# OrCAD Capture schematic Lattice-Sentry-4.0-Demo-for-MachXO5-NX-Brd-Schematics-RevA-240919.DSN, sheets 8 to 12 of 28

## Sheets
8 LFMXO5D Bank3,4: size B
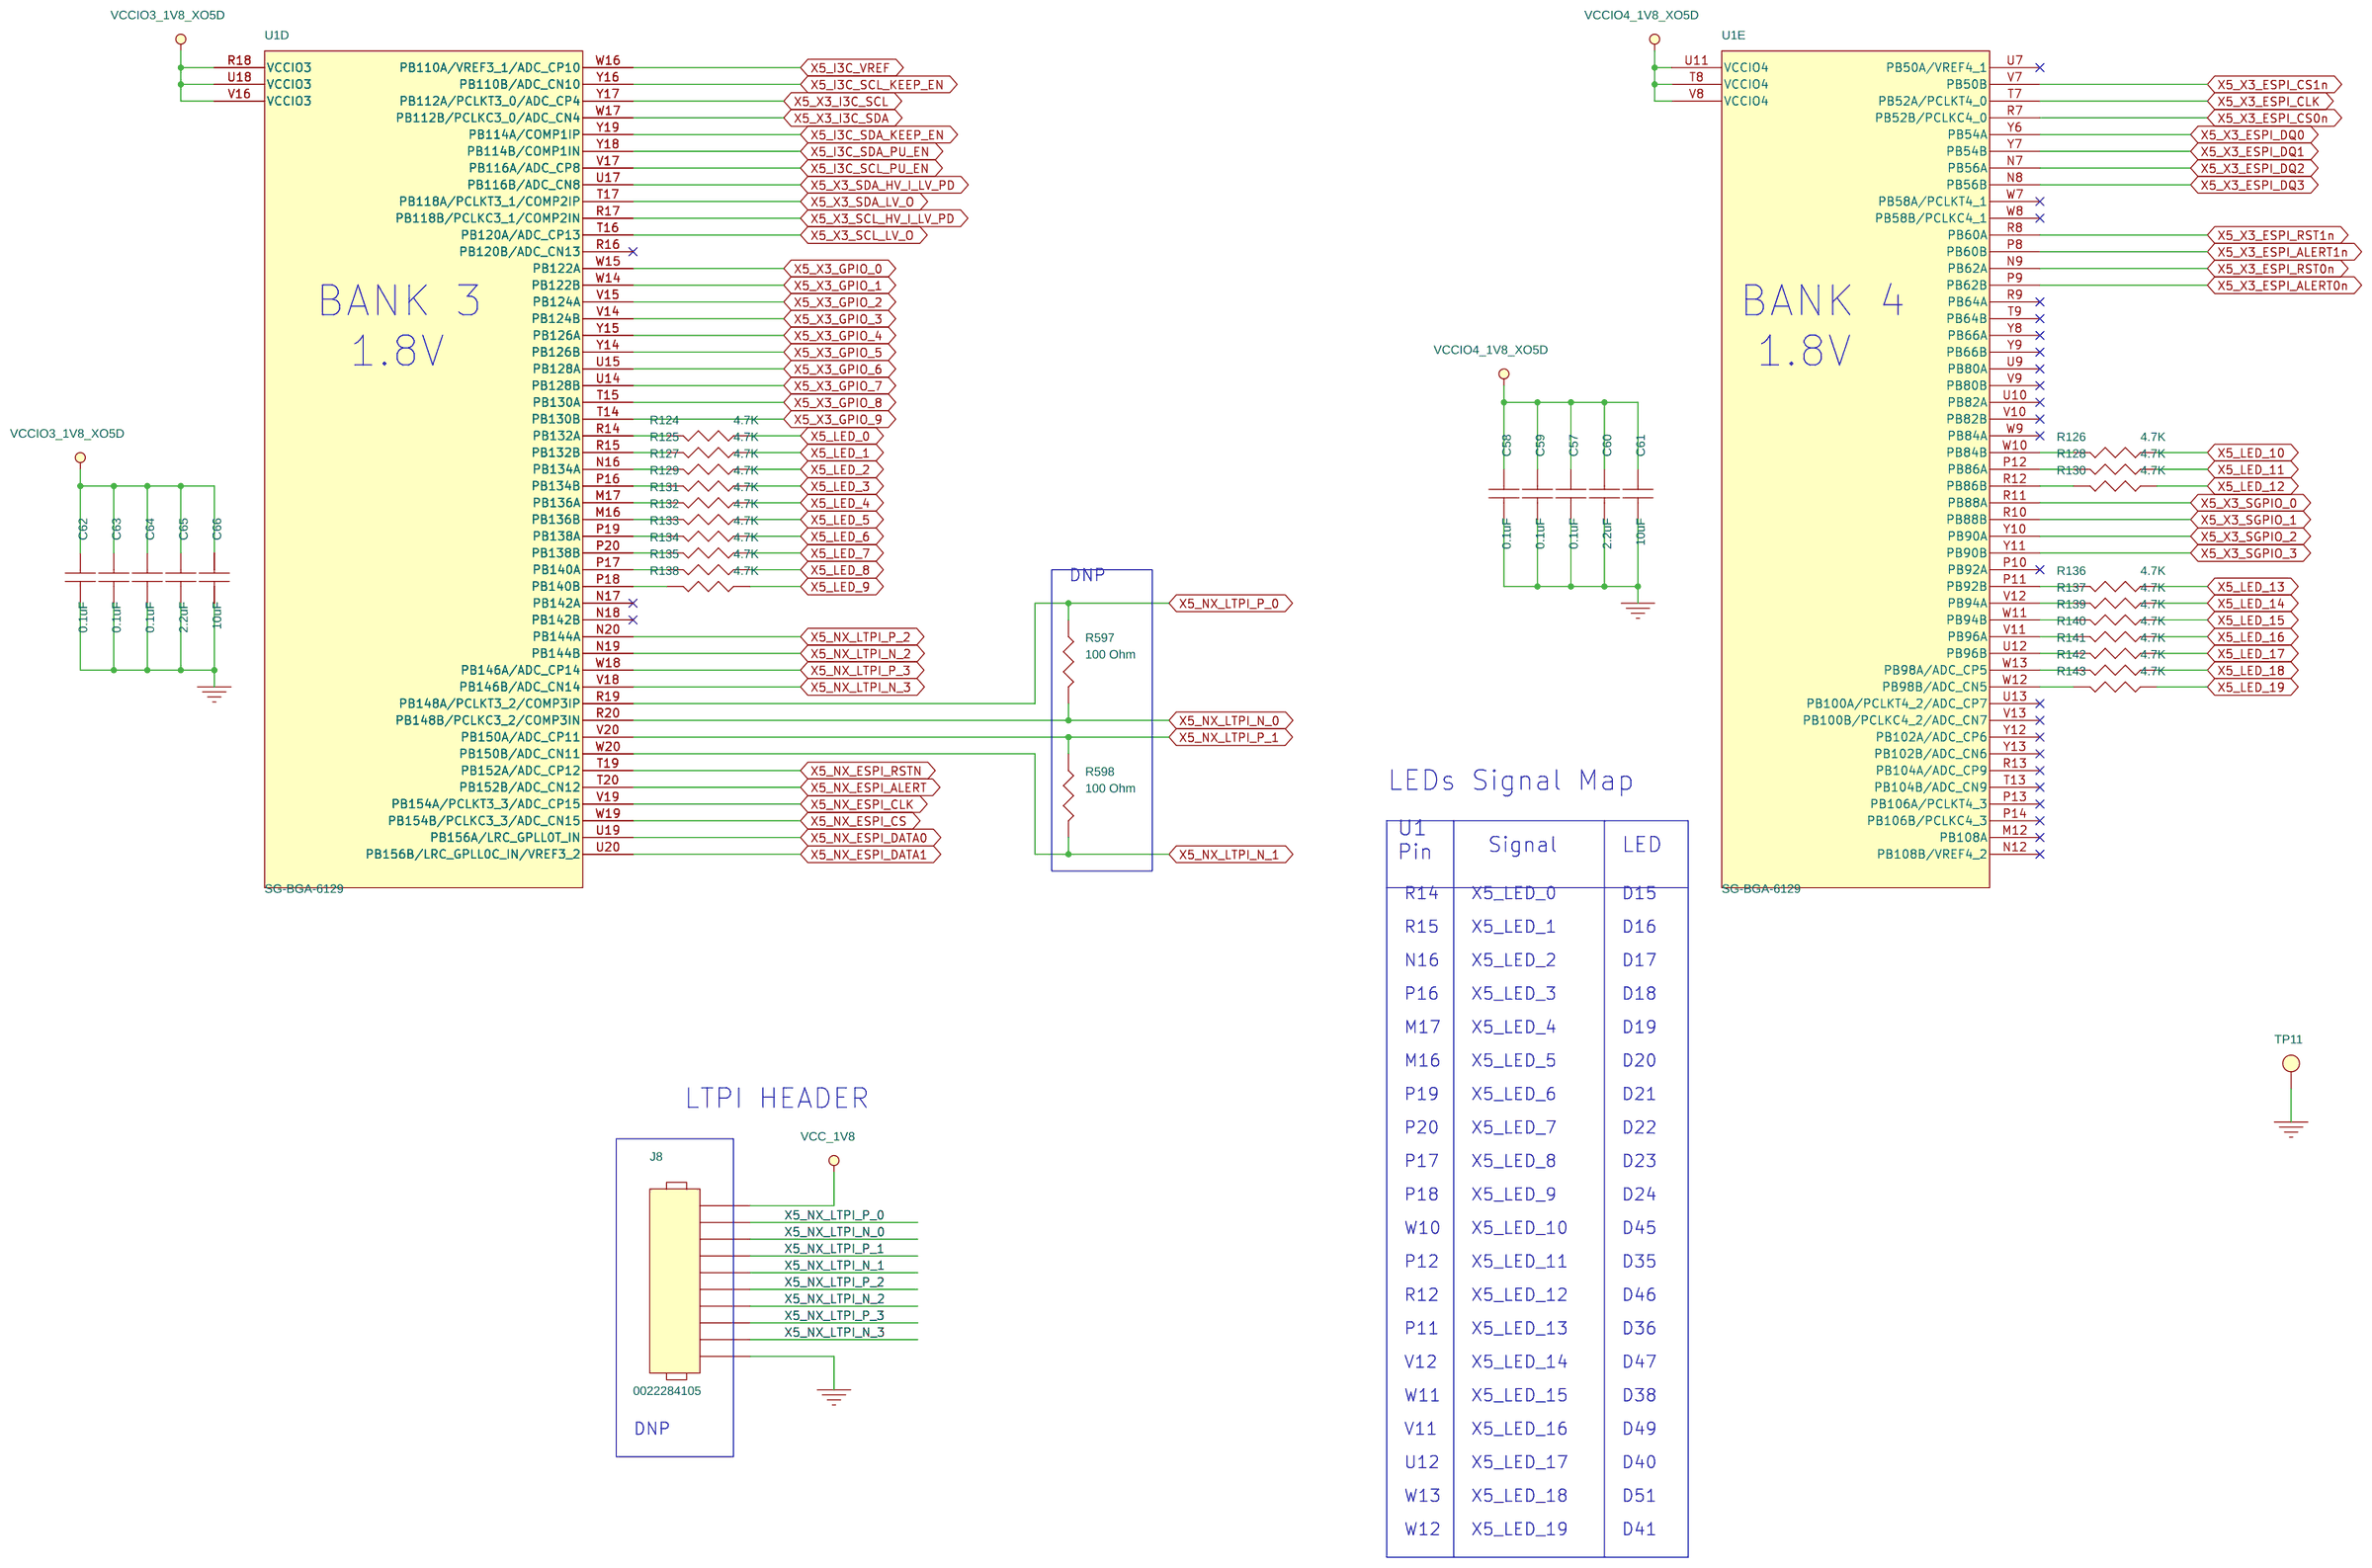
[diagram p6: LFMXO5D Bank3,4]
9 LFMXO5D Power: size B
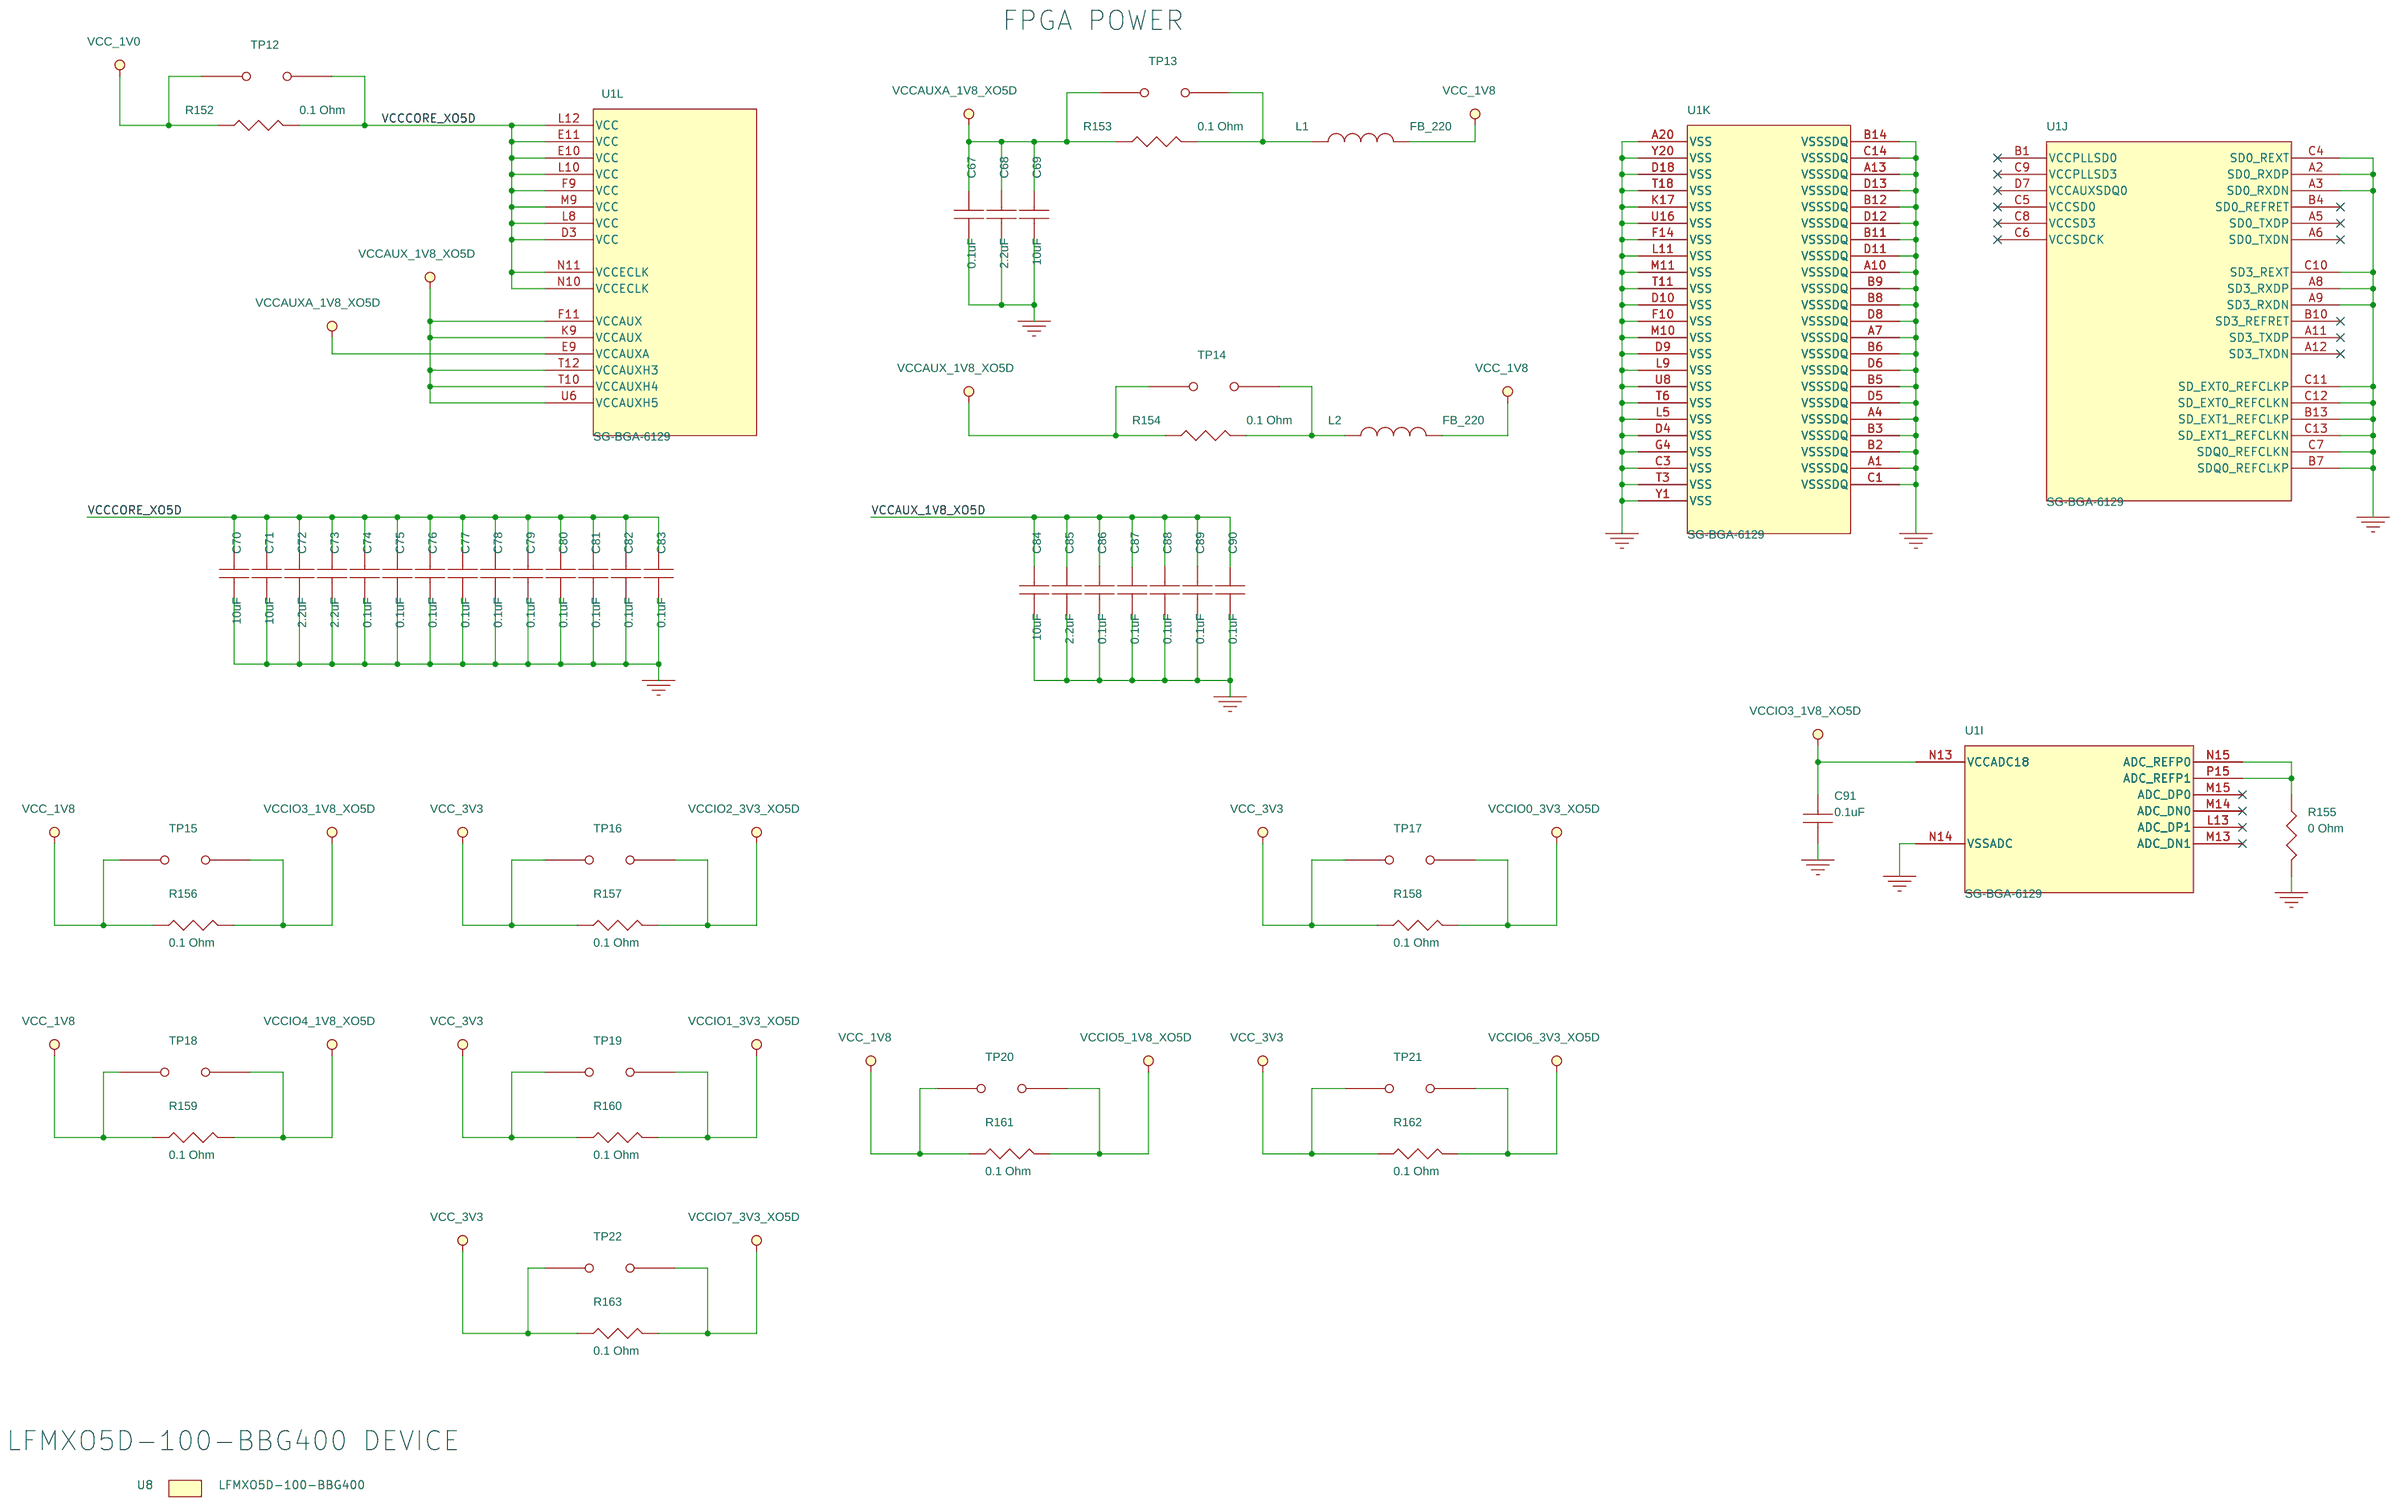
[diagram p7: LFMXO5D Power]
10 Demo FTDI: size B
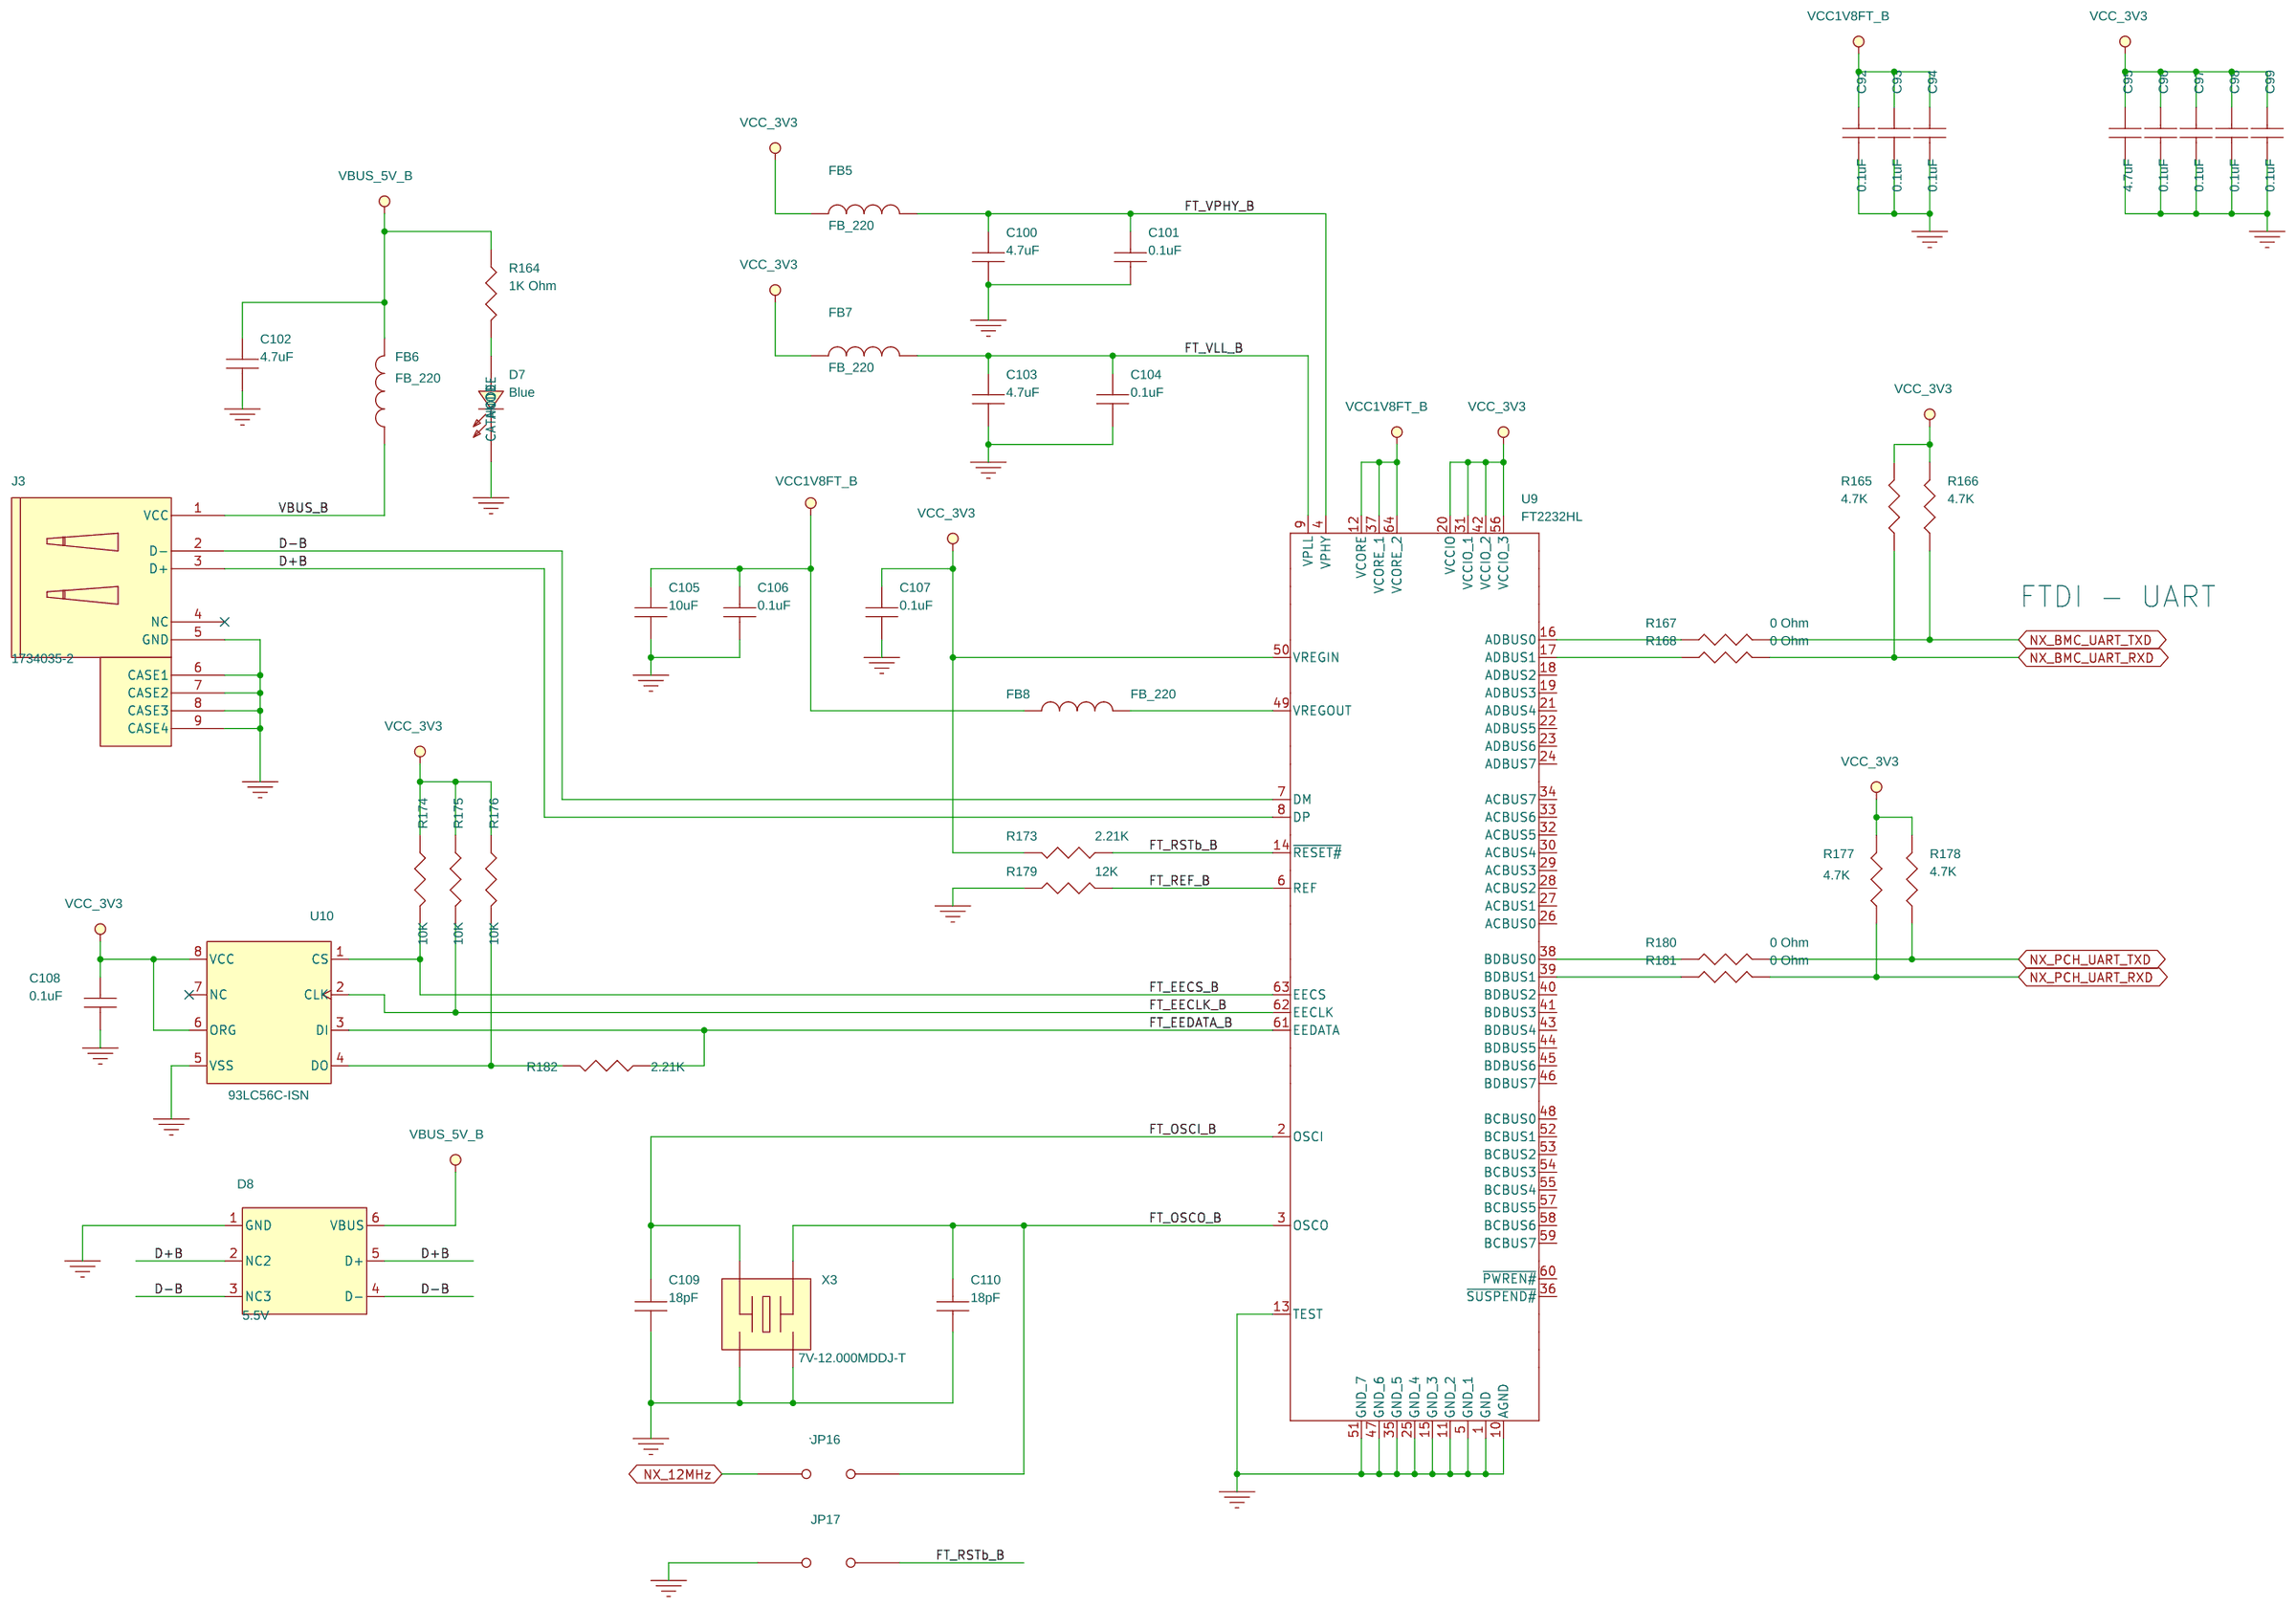
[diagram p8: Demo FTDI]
11 CertusPro-NX Bank1,5 (BMC): size B
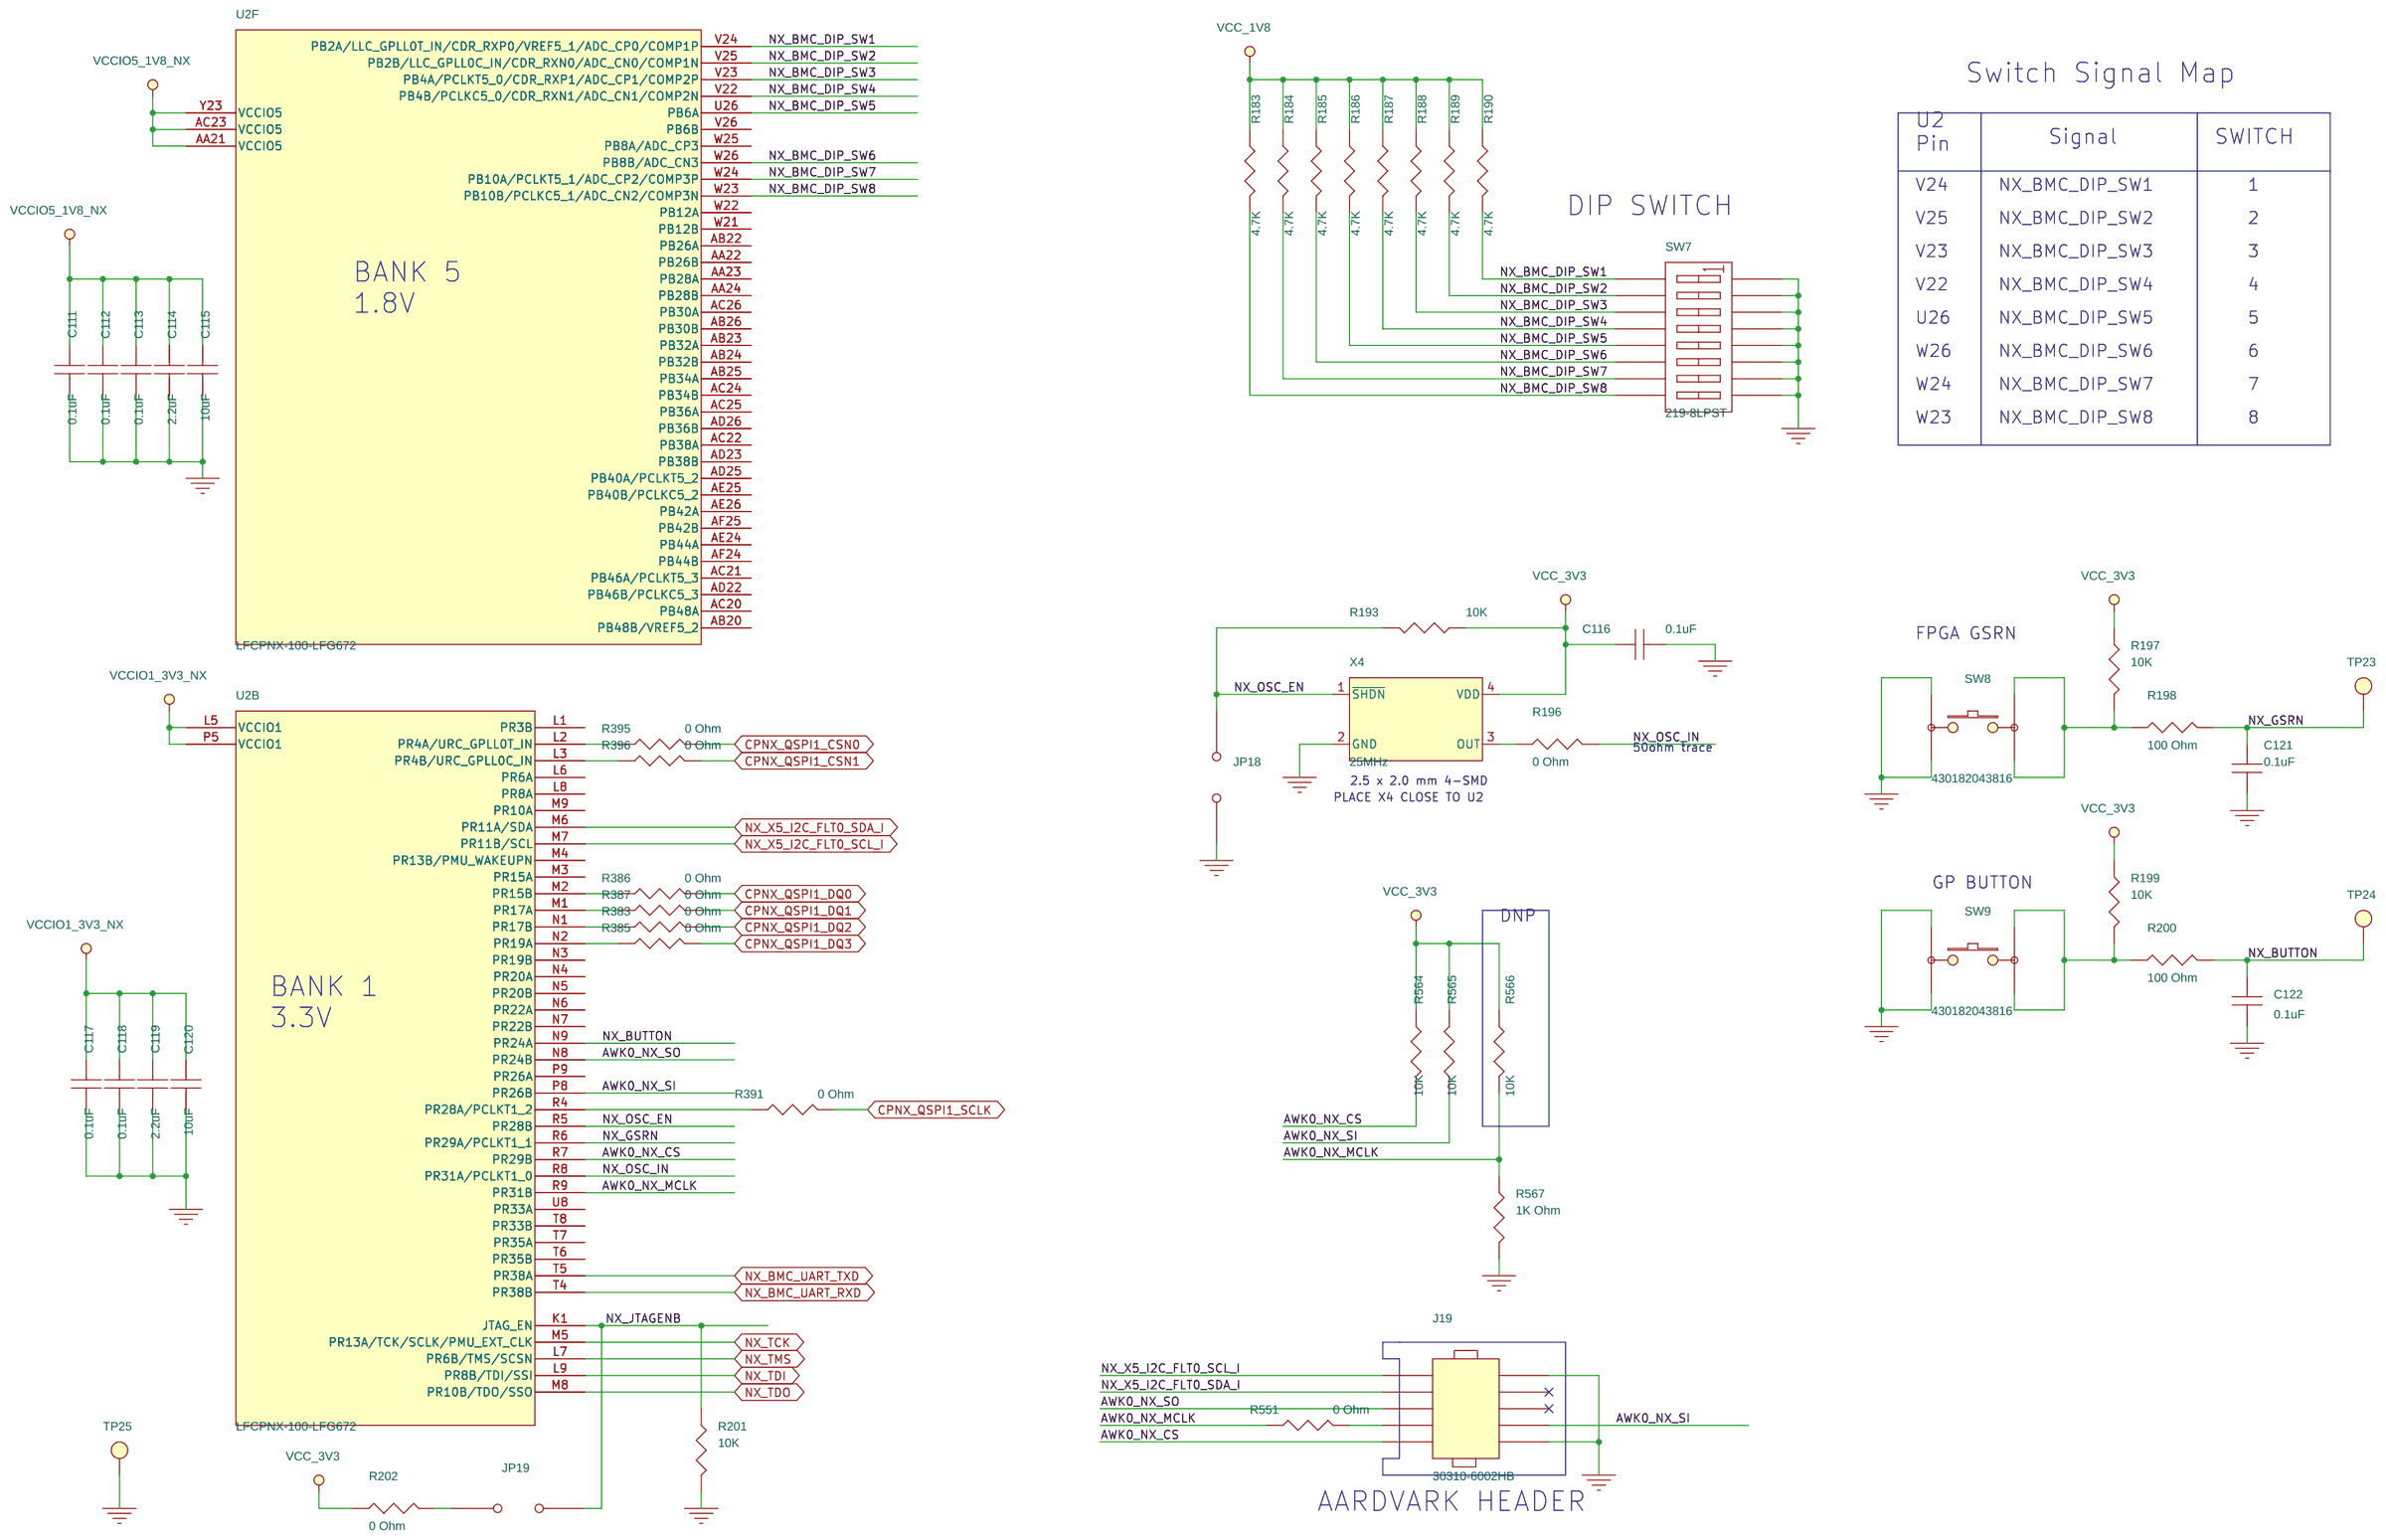
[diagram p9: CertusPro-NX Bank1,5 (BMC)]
12 CertusPro-NX Bank0 (BMC): size B
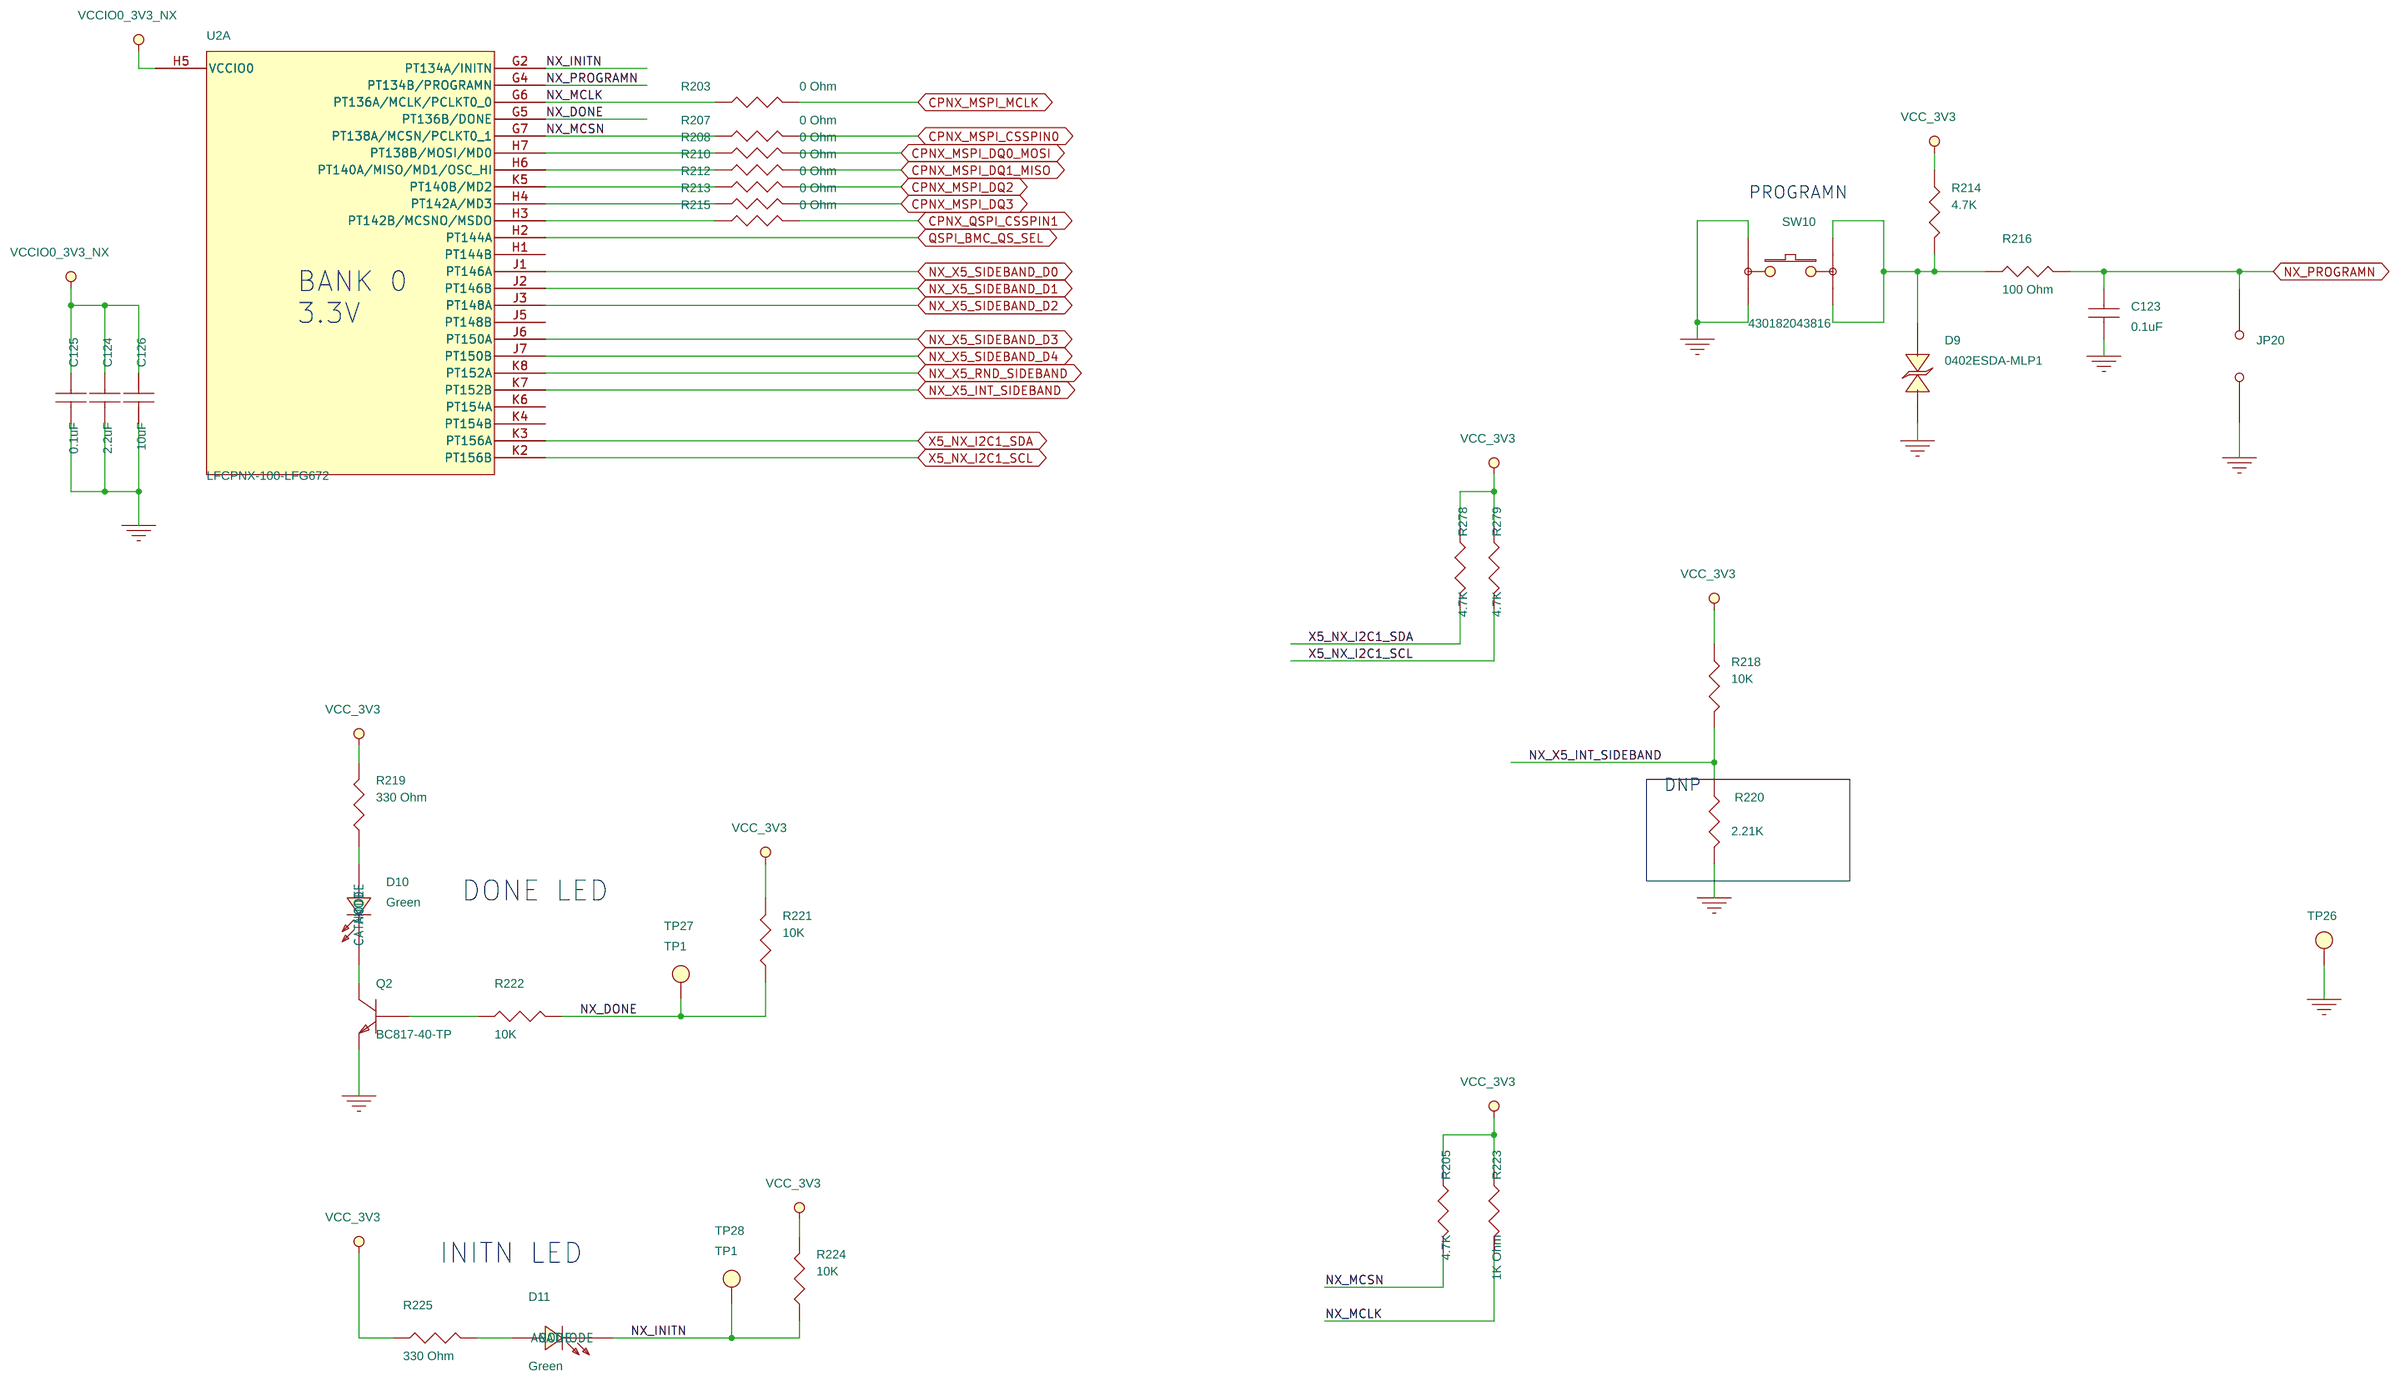
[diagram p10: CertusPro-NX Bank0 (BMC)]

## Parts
sheet Certus Pro NX Power
U2  LFCPNX-100-LFG672  [fcBGA-100p27x27-672]  (sections A,B,C,D,E,F,G,H,I,J,K,L,M,N,O)
sheet CertusPro-NX Bank0 (BMC)
C123  0.1uF  [C0402-L]
C124  2.2uF  [C0603-L]
C125  0.1uF  [C0402-L]
C126  10uF  [C0805-L]
D9  0402ESDA-MLP1  [TVS0402]
D10  Green  [LED0603]
D11  Green  [LED0603]
JP20  Jumper  [CONN2_M20-999_1x2_HRW]
Q2  BC817-40-TP  [SOT-23-3]
R203  0 Ohm  [R0402-L]
R205  4.7K  [R0402-L]
R207  0 Ohm  [R0402-L]
R208  0 Ohm  [R0402-L]
R210  0 Ohm  [R0402-L]
R212  0 Ohm  [R0402-L]
R213  0 Ohm  [R0402-L]
R214  4.7K  [R0402-L]
R215  0 Ohm  [R0402-L]
R216  100 Ohm  [R0402-L]
R218  10K  [R0402-L]
R219  330 Ohm  [R0402-L]
R220  2.21K  [R0402-L]
R221  10K  [R0402-L]
R222  10K  [R0402-L]
R223  1K Ohm  [R0402-L]
R224  10K  [R0402-L]
R225  330 Ohm  [R0402-L]
R278  4.7K  [R0402-L]
R279  4.7K  [R0402-L]
SW10  430182043816  [SOIC_82043816_WRE]
TP26  TP1  [TPd39c60]
TP27  TP1  [TPd39c60]
TP28  TP1  [TPd39c60]
sheet CertusPro-NX Bank1,5 (BMC)
C111  0.1uF  [C0402-L]
C112  0.1uF  [C0402-L]
C113  0.1uF  [C0402-L]
C114  2.2uF  [C0603-L]
C115  10uF  [C0805-L]
C116  0.1uF  [C0402-L]
C117  0.1uF  [C0402-L]
C118  0.1uF  [C0402-L]
C119  2.2uF  [C0603-L]
C120  10uF  [C0805-L]
C121  0.1uF  [C0402-L]
C122  0.1uF  [C0402-L]
J19  30310-6002HB  [CONN_30310-6002HB_3MM]
JP18  Jumper  [CONN2_M20-999_1x2_HRW]
JP19  Jumper  [CONN2_M20-999_1x2_HRW]
R183  4.7K  [R0402-L]
R184  4.7K  [R0402-L]
R185  4.7K  [R0402-L]
R186  4.7K  [R0402-L]
R187  4.7K  [R0402-L]
R188  4.7K  [R0402-L]
R189  4.7K  [R0402-L]
R190  4.7K  [R0402-L]
R193  10K  [R0402-L]
R196  0 Ohm  [R0402-L]
R197  10K  [R0402-L]
R198  100 Ohm  [R0402-L]
R199  10K  [R0402-L]
R200  100 Ohm  [R0402-L]
R201  10K  [R0402-L]
R202  0 Ohm  [R0402-L]
R383  0 Ohm  [R0402-L]
R385  0 Ohm  [R0402-L]
R386  0 Ohm  [R0402-L]
R387  0 Ohm  [R0402-L]
R391  0 Ohm  [R0402-L]
R395  0 Ohm  [R0402-L]
R396  0 Ohm  [R0402-L]
R551  0 Ohm  [R0402-L]
R564  10K  [R0402-L]
R565  10K  [R0402-L]
R566  10K  [R0402-L]
R567  1K Ohm  [R0402-L]
SW7  219-8LPST  [219-8LPST_CTS]
SW8  430182043816  [SOIC_82043816_WRE]
SW9  430182043816  [SOIC_82043816_WRE]
TP23  TP1  [TPd39c60]
TP24  TP1  [TPd39c60]
TP25  TP1  [TPd39c60]
X4  25MHz  [ECS-2520MV_ECS]
sheet Demo FTDI
C92  0.1uF  [C0402-L]
C93  0.1uF  [C0402-L]
C94  0.1uF  [C0402-L]
C95  4.7uF  [C0603-L]
C96  0.1uF  [C0402-L]
C97  0.1uF  [C0402-L]
C98  0.1uF  [C0402-L]
C99  0.1uF  [C0402-L]
C100  4.7uF  [C0603-L]
C101  0.1uF  [C0402-L]
C102  4.7uF  [C0603-L]
C103  4.7uF  [C0603-L]
C104  0.1uF  [C0402-L]
C105  10uF  [C0805-L]
C106  0.1uF  [C0402-L]
C107  0.1uF  [C0402-L]
C108  0.1uF  [C0402-L]
C109  18pF  [C0402-L]
C110  18pF  [C0402-L]
D7  Blue  [LED0603]
D8  5.5V  [UDFN6_1P2X1]
FB5  FB_220  [IND_1608_TDK]
FB6  FB_220  [IND_1608_TDK]
FB7  FB_220  [IND_1608_TDK]
FB8  FB_220  [IND_1608_TDK]
J3  1734035-2  [CONN5_USB1734035_TEC]
JP16  Jumper  [CONN2_M20-999_1x2_HRW]
JP17  Jumper  [CONN2_M20-999_1x2_HRW]
R164  1K Ohm  [R0402-L]
R165  4.7K  [R0402-L]
R166  4.7K  [R0402-L]
R167  0 Ohm  [R0402-L]
R168  0 Ohm  [R0402-L]
R173  2.21K  [R0402-L]
R174  10K  [R0402-L]
R175  10K  [R0402-L]
R176  10K  [R0402-L]
R177  4.7K  [R0402-L]
R178  4.7K  [R0402-L]
R179  12K  [R0402-L]
R180  0 Ohm  [R0402-L]
R181  0 Ohm  [R0402-L]
R182  2.21K  [R0402-L]
U9  FT2232HL  [64L-LQFP]
U10  93LC56C-ISN  [SOIC8-N]
X3  7V-12.000MDDJ-T  [SMD_0MAHE-T_TXC-L]
sheet LFMXO5D Bank3,4
C57  0.1uF  [C0402-L]
C58  0.1uF  [C0402-L]
C59  0.1uF  [C0402-L]
C60  2.2uF  [C0603-L]
C61  10uF  [C0805-L]
C62  0.1uF  [C0402-L]
C63  0.1uF  [C0402-L]
C64  0.1uF  [C0402-L]
C65  2.2uF  [C0603-L]
C66  10uF  [C0805-L]
J8  0022284105  [22-28-4105_MOL]
R124  4.7K  [R0402-L]
R125  4.7K  [R0402-L]
R126  4.7K  [R0402-L]
R127  4.7K  [R0402-L]
R128  4.7K  [R0402-L]
R129  4.7K  [R0402-L]
R130  4.7K  [R0402-L]
R131  4.7K  [R0402-L]
R132  4.7K  [R0402-L]
R133  4.7K  [R0402-L]
R134  4.7K  [R0402-L]
R135  4.7K  [R0402-L]
R136  4.7K  [R0402-L]
R137  4.7K  [R0402-L]
R138  4.7K  [R0402-L]
R139  4.7K  [R0402-L]
R140  4.7K  [R0402-L]
R141  4.7K  [R0402-L]
R142  4.7K  [R0402-L]
R143  4.7K  [R0402-L]
R597  100 Ohm  [R0402-L]
R598  100 Ohm  [R0402-L]
TP11  TP1  [TPd39c60]
sheet LFMXO5D Bank5,7
U1  SG-BGA-6129  [bga400_socket]  (sections A,B,C,D,E,F,G,H,I,J,K,L)
sheet LFMXO5D Power
C67  0.1uF  [C0402-L]
C68  2.2uF  [C0603-L]
C69  10uF  [C0805-L]
C70  10uF  [C0805-L]
C71  10uF  [C0805-L]
C72  2.2uF  [C0603-L]
C73  2.2uF  [C0603-L]
C74  0.1uF  [C0402-L]
C75  0.1uF  [C0402-L]
C76  0.1uF  [C0402-L]
C77  0.1uF  [C0402-L]
C78  0.1uF  [C0402-L]
C79  0.1uF  [C0402-L]
C80  0.1uF  [C0402-L]
C81  0.1uF  [C0402-L]
C82  0.1uF  [C0402-L]
C83  0.1uF  [C0402-L]
C84  10uF  [C0805-L]
C85  2.2uF  [C0603-L]
C86  0.1uF  [C0402-L]
C87  0.1uF  [C0402-L]
C88  0.1uF  [C0402-L]
C89  0.1uF  [C0402-L]
C90  0.1uF  [C0402-L]
C91  0.1uF  [C0402-L]
L1  FB_220  [IND_1608_TDK]
L2  FB_220  [IND_1608_TDK]
R152  0.1 Ohm  [R0603-L]
R153  0.1 Ohm  [R0603-L]
R154  0.1 Ohm  [R0603-L]
R155  0 Ohm  [R0402-L]
R156  0.1 Ohm  [R0603-L]
R157  0.1 Ohm  [R0603-L]
R158  0.1 Ohm  [R0603-L]
R159  0.1 Ohm  [R0603-L]
R160  0.1 Ohm  [R0603-L]
R161  0.1 Ohm  [R0603-L]
R162  0.1 Ohm  [R0603-L]
R163  0.1 Ohm  [R0603-L]
TP12  Jumper  [CONN2_M20-999_1x2_HRW]
TP13  Jumper  [CONN2_M20-999_1x2_HRW]
TP14  Jumper  [CONN2_M20-999_1x2_HRW]
TP15  Jumper  [CONN2_M20-999_1x2_HRW]
TP16  Jumper  [CONN2_M20-999_1x2_HRW]
TP17  Jumper  [CONN2_M20-999_1x2_HRW]
TP18  Jumper  [CONN2_M20-999_1x2_HRW]
TP19  Jumper  [CONN2_M20-999_1x2_HRW]
TP20  Jumper  [CONN2_M20-999_1x2_HRW]
TP21  Jumper  [CONN2_M20-999_1x2_HRW]
TP22  Jumper  [CONN2_M20-999_1x2_HRW]
U8  LFMXO5D-100-BBG400

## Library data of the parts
U2 = LFCPNX-100-LFG672: Lattice Lattice CertusPro-NX General Purpose FPGA on Nexus platform (28nm FD-SOI); MFR PART NO.: LFCPNX-100-9LFG672I; Manufacturer: Lattice Semiconductor; Manufacturer Part Number: LFCPNX-100-9LFG672C; PACKAGE: LFG672; PART DESCRIPTION: IC FPGA CERTUSPRO-NX; Part Number: LFCPNX-100-9LFG672C; Part Type: FPGA; Datasheet: https://www.latticesemi.com/view_document?document_id=53126
C57-C59 C62-C64 C67 C74-C83 C86-C94 C96-C99 C101 C104 C106-C108 C111-C113 C116-C118 C121-C123 C125 = CAP_NP: 0.1 µF ±10% 50V Ceramic Capacitor X7R 0402 (1005 Metric); Manufacturer: Murata; Manufacturer Part Number: GRM155R71H104KE14J; Part Number: GRM155R71H104KE14J; Part type: Ceramic; Tolerance: 10%; Voltage: 50V; Datasheet: https://search.murata.co.jp/Ceramy/image/img/A01X/G101/ENG/GRM155R71H104KE14-01.pdf
C60 C65 C68 C72 C73 C85 C114 C119 C124 = CAP_NP: 2.2 µF ±10% 25V Ceramic Capacitor X5R 0603 (1608 Metric); Manufacturer: Murata; Manufacturer Part Number: GRM188R61E225KA12J; Part Number: GRM188R61E225KA12J; Part type: Ceramic; Tolerance: 10%; Voltage: 25V; Datasheet: https://search.murata.co.jp/Ceramy/image/img/A01X/G101/ENG/GRM188R61E225KA12-01.pdf
C61 C66 C69-C71 C84 C105 C115 C120 C126 = CAP_NP: 10 µF ±10% 25V Ceramic Capacitor X5R 0805 (2012 Metric); Manufacturer: Murata; Manufacturer Part Number: GRM21BR61E106KA73K; Part Number: GRM21BR61E106KA73K; Part type: Ceramic; Tolerance: 10%; Voltage: 25V; Datasheet: https://search.murata.co.jp/Ceramy/image/img/A01X/G101/ENG/GRM21BR61E106KA73-01.pdf
D9 = DIODE_TS_BI-DIR: SUPPRESSOR ESD 30VDC 0402 HFREE; Manufacturer: Eaton; Part type: ESD; Voltage: 30V; Datasheet: https://www.eaton.com/content/dam/eaton/products/electronic-components/resources/data-sheet/eaton-0402esda-mlp-esd-suppressor-data-sheet.pdf
D10 D11 = LED_0: Green 572nm LED indication - Discrete  2.2V 0603; Manufacturer: Rohm Semiconductor; Manufacturer Part Number: SML-D12M8WT86; Part Number: SML-D12M8WT86; Part type: LED; Voltage: 2.2V; Datasheet: https://fscdn.rohm.com/en/products/databook/datasheet/opto/led/chip_mono/sml-d12x8_d13x8-e.pdf
JP20 = JUMPER: Connector Header Through Hole 2 position 0.100" (2.54mm); Manufacturer: Sullins; Manufacturer Part Number: PREC002SAAN-RC; Part Number: PREC002SAAN-RC; Datasheet: https://media.digikey.com/PDF/Data%20Sheets/Sullins%20PDFs/z%20RzCzzzSzzN-RC,%20ST,11635-B.pdf
Q2 = NPN_BEC_0: Bipolar (BJT) Transistor NPN 45 V 800 mA 100MHz 310 mW Surface Mount SOT-23; Manufacturer: Micro Commercial; Part Type: BJT_NPN; Datasheet: https://www.mccsemi.com/pdf/Products/BC817-16~BC817-40(SOT-23).pdf
R155 R167 R168 R180 R181 R196 R202 R203 R207 R208 R210 R212 R213 R215 R383 R385-R387 R391 R395 R396 R551 = R: 0 Ohms Jumper Chip Resistor 0402 (1005 Metric) Moisture Resistant Thick Film; Manufacturer: Yageo; Manufacturer Part Number: RC0402FR-070RL; Part Number: RC0402FR-070RL; Part type: Thick Film; Datasheet: https://www.yageo.com/upload/media/product/productsearch/datasheet/rchip/PYu-RC_Group_51_RoHS_L_12.pdf
R124-R143 R183-R190 R205 R214 R278 R279 = R: 4.7 kOhms ±1% 0.063W, 1/16W Chip Resistor 0402 (1005 Metric) Thick Film; Manufacturer: Yageo; Manufacturer Part Number: RC0402FR-074K7P; Part Number: RC0402FR-074K7P; Part type: Thick Film; Power: 1/16W; Tolerance: 1%; Datasheet: https://www.yageo.com/upload/media/product/products/datasheet/rchip/PYu-RC_51_RoHS_P_4.pdf
R198 R200 R216 = R: 100 Ohms ±1% 0.063W, 1/16W Chip Resistor 0402 (1005 Metric) Thick Film; Manufacturer: Yageo; Manufacturer Part Number: RC0402FR-07100KP; Part Number: RC0402FR-07100KP; Part type: Thick Film; Power: 1/16W; Tolerance: 1%; Datasheet: https://www.yageo.com/upload/media/product/productsearch/datasheet/rchip/PYu-RC_Group_51_RoHS_L_12.pdf
R174-R176 R197 R199 R201 R218 R221 R222 R224 R564 R565 = R: 10 kOhms ±1% 0.063W, 1/16W Chip Resistor 0402 (1005 Metric) Thick Film; Manufacturer: Yageo; Manufacturer Part Number: RC0402FR-0710KP; Part Number: RC0402FR-0710KP; Part type: Thick Film; Power: 1/16W; Tolerance: 1%; Datasheet: https://www.yageo.com/upload/media/product/products/datasheet/rchip/PYu-RC_51_RoHS_P_4.pdf
R219 R225 = R: 330 Ohms ±1% 0.063W, 1/16W Chip Resistor 0402 (1005 Metric) Moisture Resistant Thick Film; Manufacturer: Yageo; Manufacturer Part Number: RC0402FR-07330RL; Part Number: RC0402FR-07330RL; Part type: Thick Film; Power: 1/16W; Tolerance: 1%; Datasheet: https://www.yageo.com/upload/media/product/productsearch/datasheet/rchip/PYu-RC_Group_51_RoHS_L_12.pdf
R220 = R: 2.21 kOhms ±1% 0.063W, 1/16W Chip Resistor 0402 (1005 Metric) Thick Film; Assy: DNL; Manufacturer: Yageo; Manufacturer Part Number: RC0402FR-072K21L; Part Number: RC0402FR-072K21L; Part type: Thick Film; Power: 1/16W; Tolerance: 1%; Datasheet: https://www.yageo.com/upload/media/product/productsearch/datasheet/rchip/PYu-RC_Group_51_RoHS_L_12.pdf
R223 = R: 1 kOhms ±1% 0.063W, 1/16W Chip Resistor 0402 (1005 Metric) Thick Film; MFR PART NO.: RC0603FR-071KL; Manufacturer: Yageo; Manufacturer Part Number: RC0402FR-71K2P / RC0402FR-0733R2P; PACKAGE: 0603; PART DESCRIPTION: RES 1K OHM 1% 1/10W 0603; Part Number: RC0402FR-071KP / RC0402FR-0733R2P / RC0402FR-0733R2P; Part type: Thick Film; Power: 1/16W; Tolerance: 1%; Datasheet: https://www.yageo.com/upload/media/product/products/datasheet/rchip/PYu-RC_51_RoHS_P_4.pdf
SW8-SW10 = SW_PB-SPST-2: Tactile Switch SPST-NO Top Actuated Surface Mount; Manufacturer: Wurth; Datasheet: https://www.we-online.com/katalog/datasheet/4301x2xxx8x6.pdf
TP11 TP23-TP28 = TP1: Test Point 0.39"; Manufacturer: NA; Part Type: Test Point; Datasheet: NA
J19 = HEADER_5x2: Connector Header Through Hole 10 position 0.100" (2.54mm); Manufacturer: 3M; Part Type: Connector; Datasheet: https://multimedia.3m.com/mws/media/22504O/3mtm-100-in-loprof-hdr-100x-100strt-ra-4-wall-ts0818.pdf
JP16-JP19 TP12-TP22 = JUMPER: Connector Header Through Hole 2 position 0.100" (2.54mm); MANUFACTURER: Sullins; MFR PART NO.: 61300211121; Manufacturer Part Number: PREC002SAAN-RC; PACKAGE: TH; PART DESCRIPTION: CONN HEADER VERT 2POS 2.54MM; Part Number: PREC002SAAN-RC; Datasheet: https://media.digikey.com/PDF/Data%20Sheets/Sullins%20PDFs/z%20RzCzzzSzzN-RC,%20ST,11635-B.pdf
R193 = R: 10 kOhms ±1% 0.063W, 1/16W Chip Resistor 0402 (1005 Metric) Thick Film; MFR PART NO.: RC1608F103CS; Manufacturer: Yageo; Manufacturer Part Number: RC0402FR-0710KP; PACKAGE: 0603; PART DESCRIPTION: RES SMD 10K OHM 1% 1/10W 0603; Part Number: RC0402FR-0710KP; Part type: Thick Film; Power: 1/16W; Tolerance: 1%; Datasheet: https://www.yageo.com/upload/media/product/products/datasheet/rchip/PYu-RC_51_RoHS_P_4.pdf
R566 = R: 10 kOhms ±1% 0.063W, 1/16W Chip Resistor 0402 (1005 Metric) Thick Film; Assy: DNL; Manufacturer: Yageo; Manufacturer Part Number: RC0402FR-0710KP; Part Number: RC0402FR-0710KP; Part type: Thick Film; Power: 1/16W; Tolerance: 1%; Datasheet: https://www.yageo.com/upload/media/product/products/datasheet/rchip/PYu-RC_51_RoHS_P_4.pdf
R164 R567 = R: 1 kOhms ±1% 0.063W, 1/16W Chip Resistor 0402 (1005 Metric) Thick Film; Manufacturer: Yageo; Manufacturer Part Number: RC0402FR-71K2P / RC0402FR-0733R2P; Part Number: RC0402FR-071KP / RC0402FR-0733R2P / RC0402FR-0733R2P; Part type: Thick Film; Power: 1/16W; Tolerance: 1%; Datasheet: https://www.yageo.com/upload/media/product/products/datasheet/rchip/PYu-RC_51_RoHS_P_4.pdf
SW7 = SW_DIP-8: Dip Switch SPST 8 Position Surface Mount Slide (Standard) Actuator 100mA 20VDC / Dip Switch SPST 5 Position Surface Mount Slide (Standard) Actuator 100mA 20VDC; MFR PART NO.: TDA08H0SB1; Manufacturer: CST; PACKAGE: SMD; PART DESCRIPTION: SWITCH SLIDE DIP SPST 25MA 24V; Datasheet: https://www.ctscorp.com/wp-content/uploads/219.pdf
X4 = OSC4PIN_SM: 25 MHz XO (Standard) HCMOS Oscillator 1.6V ~ 3.6V Enable/Disable 4-SMD, No Lead; Manufacturer: ECS; Manufacturer Part Number: ECS-2520MV-250-CM-TR; Part Number: ECS-2520MV-250-CM-TR; Part Type: Oscillator; Datasheet: https://ecsxtal.com/store/pdf/ECS-3225MV.pdf
C95 C100 C102 C103 = CAP_NP: 4.7 µF ±10% 25V Ceramic Capacitor X5R 0603 (1608 Metric); Manufacturer: TDK; Manufacturer Part Number: C1608X5R1E475K080AC; Part Number: C1608X5R1E475K080AC; Part type: Ceramic; Tolerance: 10%; Voltage: 25V; Datasheet: https://product.tdk.com/system/files/dam/doc/product/capacitor/ceramic/mlcc/catalog/mlcc_commercial_general_en.pdf
C109 C110 = CAP_NP: 18 pF ±5% 50V Ceramic Capacitor C0G, NP0 0402 (1005 Metric); Manufacturer: Yageo; Manufacturer Part Number: CC0402JRNPO9BN180; Part Number: CC0402JRNPO9BN180; Part type: Ceramic; Tolerance: 5%; Voltage: 50V; Datasheet: https://www.yageo.com/upload/media/product/productsearch/datasheet/mlcc/UPY-GP_NP0_16V-to-50V_18.pdf
D7 = LED_0: Blue 470nm LED Indication - Discrete 2.9V 0603 (1608 Metric); Manufacturer: Lumex; Manufacturer Part Number: SMLD12BN1WT86; Part Number: SMLD12BN1WT86; Part type: LED; Voltage: 2.9V; Datasheet: https://www.rohm.com/datasheet?p=SMLD12BN1W&dist=Digi-key&media=referral&source=digi-key.com&campaign=Digi-key
D8 = ESDR0502: Clamp Ipp Tvs Diode Surface Mount 6-UDFN (1.2x1); Current: 100W; MANUFACTURER: ONSEMI; MFR PART NO.: ESDR0502NMUTBG; Manufacturer Part Number: ESDR0502NMUTAG; PACKAGE: 6-UFDFN; PART DESCRIPTION: TVS DIODE 5.5VWM 6UDFN; Part Number: ESDR0502NMUTAG; Part type: TVS; Datasheet: https://www.onsemi.com/pdf/datasheet/esdr0502n-d.pdf
FB5-FB8 L1 L2 = INDUCTOR: 220 Ohms @ 100 MHz 1 Power Line Ferrite Bead 0603 (1608 Metric) 2.2A 50mOhm; Current: 2.2A; DCR: 50 mOhm; Manufacturer: Murata Electronics; Manufacturer Part Number: BLM18KG221SN1D; Part Number: BLM18KG221SN1D; Datasheet: https://www.murata.com/products/productdata/8796738650142/ENFA0003.pdf
J3 = USB_MINI_B: USB - mini B USB 2.0 Receptacle Connector 5 Position Surface Mount, Right Angle; MANUFACTURER: TE Connectivity; MFR PART NO.: 690-005-299-043; PACKAGE: SMD; PART DESCRIPTION: CONN RCPT USB2.0 MINI B SMD R/A; Part Type: Connector; Populate: <Populate>; Datasheet: https://www.te.com/commerce/DocumentDelivery/DDEController?Action=srchrtrv&DocNm=1734035&DocType=Customer+Drawing&DocLang=English
R165 R166 R177 R178 = R: 4.7 kOhms ±1% 0.063W, 1/16W Chip Resistor 0402 (1005 Metric) Thick Film; MFR PART NO.: CRCW06032K20FKEA; Manufacturer: Yageo; Manufacturer Part Number: RC0402FR-074K7P; PACKAGE: 0603; PART DESCRIPTION: RES SMD 2.2K OHM 1% 1/10W 0603; Part Number: RC0402FR-074K7P; Part type: Thick Film; Populate: <Populate>; Power: 1/16W; Tolerance: 1%; Datasheet: https://www.yageo.com/upload/media/product/products/datasheet/rchip/PYu-RC_51_RoHS_P_4.pdf
R173 R182 = R: 2.21 kOhms ±1% 0.063W, 1/16W Chip Resistor 0402 (1005 Metric) Thick Film; Manufacturer: Yageo; Manufacturer Part Number: RC0402FR-072K21L; Part Number: RC0402FR-072K21L; Part type: Thick Film; Power: 1/16W; Tolerance: 1%; Datasheet: https://www.yageo.com/upload/media/product/productsearch/datasheet/rchip/PYu-RC_Group_51_RoHS_L_12.pdf
R179 = R: 12 kOhms ±1% 0.063W, 1/16W Chip Resistor 0402 (1005 Metric) Moisture Resistant Thick Film; Manufacturer: Yageo; Manufacturer Part Number: RC0402FR-0712KL; Part Number: RC0402FR-0712KL; Part type: Thick Film; Power: 1/16W; Tolerance: 1%; Datasheet: https://www.yageo.com/upload/media/product/productsearch/datasheet/rchip/PYu-RC_Group_51_RoHS_L_12.pdf
U9 = FT2232HQ-REEL_3: IC USB HS DUAL UART/FIFO 64-LQFP; Manufacturer: FTDI; Manufacturer Part Number: FT2232HL-REEL; Part Number: FT2232HL-REEL; Part Type: USB Bridge; Datasheet: https://www.ftdichip.com/Support/Documents/DataSheets/ICs/DS_FT2232H.pdf
U10 = 93LC56C-I_SN: EEPROM Memory IC 2Kbit Microwire 3 MHz 8-SOIC; Manufacturer: Microchip; Part Type: EEPROM; Datasheet: https://ww1.microchip.com/downloads/en/DeviceDoc/21794G.pdf
X3 = CRYSTAL1-4_SM: 12 MHz ±20ppm Crystal 18pF 150 Ohms 4-SMD, No Lead; Manufacturer: TXC; Part Type: Crystal; Datasheet: http://www.txccrystal.com/images/pdf/7v.pdf
J8 = HEADER_10: Connector Header Through Hole 10 position 0.100" (2.54mm); Assy: DNL; MFR PART NO.: 0022284101; Manufacturer: Molex; PACKAGE: TH; PART DESCRIPTION: CONN HEADER VERT 10POS 2.54MM; Part Type: Connector; Datasheet: https://www.molex.com/pdm_docs/sd/022284105_sd.pdf
R597 R598 = R: 100 Ohms ±1% 0.063W, 1/16W Chip Resistor 0402 (1005 Metric) Thick Film; Assy: DNL; Manufacturer: Yageo; Manufacturer Part Number: RC0402FR-07100KP; Part Number: RC0402FR-07100KP; Part type: Thick Film; Power: 1/16W; Tolerance: 1%; Datasheet: https://www.yageo.com/upload/media/product/productsearch/datasheet/rchip/PYu-RC_Group_51_RoHS_L_12.pdf
U1 = LFMXO5D-100-BBG400: GHz BGA Socket - Direct mount, solderless; Manufacturer: Ironwood Electronics; PACKAGE: BBG400; PART DESCRIPTION: BGA Socket; gold plated wire elastomer; Datasheet: https://www.ironwoodelectronics.com/catalog/Content/Drawings/SG-BGA-6129Dwg.pdf
R152-R154 R156-R163 = R: 100 mOhms ±1% 0.2W, 1/5W Chip Resistor 0603 (1608 Metric) Current Sense Metal Film; Manufacturer: Ohmite; Manufacturer Part Number: KDV06FR100ET; Part Number: KDV06FR100ET; Part type: Metal Film; Tolerance: 1%; Datasheet: https://www.ohmite.com/assets/docs/res_kdv.pdf?r=false
U8 = BOM-ONLY: Manufacturer: Lattice; Part Number: LFMXO5D-100-BBG400-BOM-ONLY; Part Type: FPGA

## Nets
GND: C57.2 C58.2 C59.2 C60.2 C61.2 C62.2 C63.2 C64.2 C65.2 C66.2 C67.2 C68.2 C69.2 C70.2 C71.2 C72.2 C73.2 C74.2 C75.2 C76.2 C77.2 C78.2 C79.2 C80.2 C81.2 C82.2 C83.2 C84.2 C85.2 C86.2 C87.2 C88.2 C89.2 C90.2 C91.2 C92.2 C93.2 C94.2 C95.2 C96.2 C97.2 C98.2 C99.2 C100.2 C101.2 C102.2 C103.2 C104.2 C105.2 C106.2 C107.2 C108.2 C109.1 C110.1 C111.2 C112.2 C113.2 C114.2 C115.2 C116.2 C117.2 C118.2 C119.2 C120.2 C121.2 C122.2 C123.2 C124.2 C125.2 C126.2 D7.K(CATHODE) D8.1(GND) D9.2 J3.5(GND) J3.6(CASE1) J3.7(CASE2) J3.8(CASE3) J3.9(CASE4) J8.10 J19.2 J19.10 JP17.2 JP18.1 JP20.2 Q2.E R155.2 R179.1 R201.2 R220.2 R567.2 SW7.9(B8) SW7.10(B7) SW7.11(B6) SW7.12(B5) SW7.13(B4) SW7.14(B3) SW7.15(B2) SW7.16(B1) SW8.1 SW8.3 SW9.1 SW9.3 SW10.2 SW10.4 TP11.1 TP25.1 TP26.1 U1.A1(VSSSDQ) U1.A2(SD0_RXDP) U1.A3(SD0_RXDN) U1.A4(VSSSDQ) U1.A7(VSSSDQ) U1.A8(SD3_RXDP) U1.A9(SD3_RXDN) U1.A10(VSSSDQ) U1.A13(VSSSDQ) U1.A20(VSS) U1.B2(VSSSDQ) U1.B3(VSSSDQ) U1.B5(VSSSDQ) U1.B6(VSSSDQ) U1.B7(SDQ0_REFCLKP) U1.B8(VSSSDQ) U1.B9(VSSSDQ) U1.B11(VSSSDQ) U1.B12(VSSSDQ) U1.B13(SD_EXT1_REFCLKP) U1.B14(VSSSDQ) U1.C1(VSSSDQ) U1.C3(VSS) U1.C4(SD0_REXT) U1.C7(SDQ0_REFCLKN) U1.C10(SD3_REXT) U1.C11(SD_EXT0_REFCLKP) U1.C12(SD_EXT0_REFCLKN) U1.C13(SD_EXT1_REFCLKN) U1.C14(VSSSDQ) U1.D4(VSS) U1.D5(VSSSDQ) U1.D6(VSSSDQ) U1.D8(VSSSDQ) U1.D9(VSS) U1.D10(VSS) U1.D11(VSSSDQ) U1.D12(VSSSDQ) U1.D13(VSSSDQ) U1.D18(VSS) U1.F10(VSS) U1.F14(VSS) U1.G4(VSS) U1.K17(VSS) U1.L5(VSS) U1.L9(VSS) U1.L11(VSS) U1.M10(VSS) U1.M11(VSS) U1.N14(VSSADC) U1.T3(VSS) U1.T6(VSS) U1.T11(VSS) U1.T18(VSS) U1.U8(VSS) U1.U16(VSS) U1.Y1(VSS) U1.Y20(VSS) U9.1(GND) U9.5(GND_1) U9.10(AGND) U9.11(GND_2) U9.13(TEST) U9.15(GND_3) U9.25(GND_4) U9.35(GND_5) U9.47(GND_6) U9.51(GND_7) U10.5(VSS) X3.2 X3.4 X4.2(GND) ; also on sheet 3 4 5 6 7 13 14 15 16 17 18 19 20 21 22 23 24 25 26 27 28
VBUS_5V_B: C102.1 D8.6(VBUS) FB6.1 R164.1
VBUS_B: FB6.2 J3.1(VCC)
VCC1V8FT_B: C92.1 C93.1 C94.1 C105.1 C106.1 FB8.2 U9.12(VCORE) U9.37(VCORE_1) U9.64(VCORE_2)
VCC_1V0: R152.1 TP12.2 ; also on sheet 16 27 28
VCC_1V8: J8.1 L1.1 L2.1 R156.1 R159.1 R161.1 R183.1 R184.1 R185.1 R186.1 R187.1 R188.1 R189.1 R190.1 TP15.2 TP18.2 TP20.2 ; also on sheet 6 15 16 18 20 26 27 28
VCC_3V3: C95.1 C96.1 C97.1 C98.1 C99.1 C107.1 C108.1 C116.1 FB5.2 FB7.2 R157.1 R158.1 R160.1 R162.1 R163.1 R165.2 R166.2 R173.2 R174.1 R175.1 R176.1 R177.2 R178.2 R193.1 R197.1 R199.1 R202.1 R205.1 R214.1 R218.1 R219.2 R221.2 R223.1 R224.2 R225.1 R278.1 R279.1 R564.1 R565.1 R566.1 TP16.2 TP17.2 TP19.2 TP21.2 TP22.2 U9.20(VCCIO) U9.31(VCCIO_1) U9.42(VCCIO_2) U9.50(VREGIN) U9.56(VCCIO_3) U10.6(ORG) U10.8(VCC) X4.4(VDD) ; also on sheet 3 4 5 6 7 13 14 16 17 19 20 21 22 23 24 25 26 28
VCCAUX_1V8_XO5D: C84.1 C85.1 C86.1 C87.1 C88.1 C89.1 C90.1 R154.2 TP14.2 U1.F11(VCCAUX) U1.K9(VCCAUX) U1.T10(VCCAUXH4) U1.T12(VCCAUXH3) U1.U6(VCCAUXH5)
VCCAUXA_1V8_XO5D: C67.1 C68.1 C69.1 R153.2 TP13.2 U1.E9(VCCAUXA)
VCCCORE_XO5D: C70.1 C71.1 C72.1 C73.1 C74.1 C75.1 C76.1 C77.1 C78.1 C79.1 C80.1 C81.1 C82.1 C83.1 R152.2 TP12.1 U1.D3(VCC) U1.E10(VCC) U1.E11(VCC) U1.F9(VCC) U1.L8(VCC) U1.L10(VCC) U1.L12(VCC) U1.M9(VCC) U1.N10(VCCECLK) U1.N11(VCCECLK)
VCCIO0_3V3_NX: C124.1 C125.1 C126.1 U2.H5(VCCIO0) ; also on sheet 16
VCCIO0_3V3_XO5D: R158.2 TP17.1 ; also on sheet 5
VCCIO1_3V3_NX: C117.1 C118.1 C119.1 C120.1 U2.L5(VCCIO1) U2.P5(VCCIO1) ; also on sheet 16
VCCIO1_3V3_XO5D: R160.2 TP19.1 ; also on sheet 4
VCCIO2_3V3_XO5D: R157.2 TP16.1 ; also on sheet 7
VCCIO3_1V8_XO5D: C62.1 C63.1 C64.1 C65.1 C66.1 C91.1 R156.2 TP15.1 U1.N13(VCCADC18) U1.R18(VCCIO3) U1.U18(VCCIO3) U1.V16(VCCIO3)
VCCIO4_1V8_XO5D: C57.1 C58.1 C59.1 C60.1 C61.1 R159.2 TP18.1 U1.T8(VCCIO4) U1.U11(VCCIO4) U1.V8(VCCIO4)
VCCIO5_1V8_NX: C111.1 C112.1 C113.1 C114.1 C115.1 U2.AA21(VCCIO5) U2.AC23(VCCIO5) U2.Y23(VCCIO5) ; also on sheet 16
VCCIO5_1V8_XO5D: R161.2 TP20.1 ; also on sheet 6
VCCIO6_3V3_XO5D: R162.2 TP21.1 ; also on sheet 7
VCCIO7_3V3_XO5D: R163.2 TP22.1 ; also on sheet 6
AWK0_NX_CS: J19.9 R564.2 U2.R7(PR29B)
AWK0_NX_MCLK: R551.2 R566.2 R567.1 U2.R9(PR31B)
AWK0_NX_SI: J19.8 R565.2 U2.P8(PR26B)
AWK0_NX_SO: J19.5 U2.N8(PR24B)
CPNX_MSPI_CSSPIN0: R207.2 ; also on sheet 22 23
CPNX_MSPI_DQ0_MOSI: R208.2 ; also on sheet 22 23
CPNX_MSPI_DQ1_MISO: R210.2 ; also on sheet 22 23
CPNX_MSPI_DQ2: R212.2 ; also on sheet 22 23
CPNX_MSPI_DQ3: R213.2 ; also on sheet 22 23
CPNX_MSPI_MCLK: R203.2 ; also on sheet 22 23
CPNX_QSPI1_CSN0: R395.2 ; also on sheet 22
CPNX_QSPI1_CSN1: R396.2 ; also on sheet 22
CPNX_QSPI1_DQ0: R386.2 ; also on sheet 22
CPNX_QSPI1_DQ1: R387.2 ; also on sheet 22
CPNX_QSPI1_DQ2: R383.2 ; also on sheet 22
CPNX_QSPI1_DQ3: R385.2 ; also on sheet 22
CPNX_QSPI1_SCLK: R391.2 ; also on sheet 22
CPNX_QSPI_CSSPIN1: R215.2 ; also on sheet 22 23
D+B: D8.2(NC2) D8.5(D+) J3.3(D+) U9.8(DP)
D-B: D8.3(NC3) D8.4(D-) J3.2(D-) U9.7(DM)
FT_EECLK_B: R175.2 U9.62(EECLK) U10.2(CLK)
FT_EECS_B: R174.2 U9.63(EECS) U10.1(CS)
FT_EEDATA_B: R182.1 U9.61(EEDATA) U10.3(DI)
FT_OSCI_B: C109.2 U9.2(OSCI) X3.1
FT_OSCO_B: C110.2 JP16.1 U9.3(OSCO) X3.3
FT_REF_B: R179.2 U9.6(REF)
FT_RSTb_B: JP17.1 R173.1 U9.14(~{RESET#})
FT_VLL_B: C103.1 C104.1 FB7.1 U9.9(VPLL)
FT_VPHY_B: C100.1 C101.1 FB5.1 U9.4(VPHY)
NX_12MHz: JP16.2 ; also on sheet 13
NX_BMC_DIP_SW1: R190.2 SW7.1(A1) U2.V24(PB2A/LLC_GPLL0T_IN/CDR_RXP0/VREF5_1/ADC_CP0/COMP1P)
NX_BMC_DIP_SW2: R189.2 SW7.2(A2) U2.V25(PB2B/LLC_GPLL0C_IN/CDR_RXN0/ADC_CN0/COMP1N)
NX_BMC_DIP_SW3: R188.2 SW7.3(A3) U2.V23(PB4A/PCLKT5_0/CDR_RXP1/ADC_CP1/COMP2P)
NX_BMC_DIP_SW4: R187.2 SW7.4(A4) U2.V22(PB4B/PCLKC5_0/CDR_RXN1/ADC_CN1/COMP2N)
NX_BMC_DIP_SW5: R186.2 SW7.5(A5) U2.U26(PB6A)
NX_BMC_DIP_SW6: R185.2 SW7.6(A6) U2.W26(PB8B/ADC_CN3)
NX_BMC_DIP_SW7: R184.2 SW7.7(A7) U2.W24(PB10A/PCLKT5_1/ADC_CP2/COMP3P)
NX_BMC_DIP_SW8: R183.2 SW7.8(A8) U2.W23(PB10B/PCLKC5_1/ADC_CN2/COMP3N)
NX_BMC_UART_RXD: R165.1 R168.2 U2.T4(PR38B)
NX_BMC_UART_TXD: R166.1 R167.2 U2.T5(PR38A)
NX_BUTTON: C122.1 R200.2 TP24.1 U2.N9(PR24A)
NX_DONE: R221.1 R222.2 TP27.1 U2.G5(PT136B/DONE)
NX_GSRN: C121.1 R198.2 TP23.1 U2.R6(PR29A/PCLKT1_1)
NX_INITN: D11.K(CATHODE) R224.1 TP28.1 U2.G2(PT134A/INITN)
NX_JTAGENB: JP19.2 R201.1 U2.K1(JTAG_EN)
NX_MCLK: R203.1 R223.2 U2.G6(PT136A/MCLK/PCLKT0_0)
NX_MCSN: R205.2 R207.1 U2.G7(PT138A/MCSN/PCLKT0_1)
NX_OSC_EN: JP18.2 R193.2 U2.R5(PR28B) X4.1(~{SHDN})
NX_OSC_IN: R196.2 U2.R8(PR31A/PCLKT1_0)
NX_PCH_UART_RXD: R177.1 R181.2 ; also on sheet 14
NX_PCH_UART_TXD: R178.1 R180.2 ; also on sheet 14
NX_PROGRAMN: C123.1 JP20.1 R216.2 U2.G4(PT134B/PROGRAMN) ; also on sheet 5
NX_TCK: U2.M5(PR13A/TCK/SCLK/PMU_EXT_CLK) ; also on sheet 24
NX_TDI: U2.L9(PR8B/TDI/SSI) ; also on sheet 24
NX_TDO: U2.M8(PR10B/TDO/SSO) ; also on sheet 24
NX_TMS: U2.L7(PR6B/TMS/SCSN) ; also on sheet 24
NX_X5_I2C_FLT0_SCL_I: J19.1 U2.M7(PR11B/SCL) ; also on sheet 4
NX_X5_I2C_FLT0_SDA_I: J19.3 U2.M6(PR11A/SDA) ; also on sheet 4
NX_X5_INT_SIDEBAND: R218.2 R220.1 U2.K7(PT152B) ; also on sheet 5
NX_X5_RND_SIDEBAND: U2.K8(PT152A) ; also on sheet 5
NX_X5_SIDEBAND_D0: U2.J1(PT146A) ; also on sheet 5
NX_X5_SIDEBAND_D1: U2.J2(PT146B) ; also on sheet 5
NX_X5_SIDEBAND_D2: U2.J3(PT148A) ; also on sheet 5
NX_X5_SIDEBAND_D3: U2.J6(PT150A) ; also on sheet 5
NX_X5_SIDEBAND_D4: U2.J7(PT150B) ; also on sheet 5
QSPI_BMC_QS_SEL: U2.H2(PT144A) ; also on sheet 22
X5_I3C_SCL_KEEP_EN: U1.Y16(PB110B/ADC_CN10) ; also on sheet 27
X5_I3C_SCL_PU_EN: U1.V17(PB116A/ADC_CP8) ; also on sheet 27
X5_I3C_SDA_KEEP_EN: U1.Y19(PB114A/COMP1IP) ; also on sheet 27
X5_I3C_SDA_PU_EN: U1.Y18(PB114B/COMP1IN) ; also on sheet 27
X5_I3C_VREF: U1.W16(PB110A/VREF3_1/ADC_CP10) ; also on sheet 27
X5_LED_0: R124.1 ; also on sheet 25
X5_LED_1: R125.1 ; also on sheet 25
X5_LED_2: R127.1 ; also on sheet 25
X5_LED_3: R129.1 ; also on sheet 25
X5_LED_4: R131.1 ; also on sheet 25
X5_LED_5: R132.1 ; also on sheet 25
X5_LED_6: R133.1 ; also on sheet 25
X5_LED_7: R134.1 ; also on sheet 25
X5_LED_8: R135.1 ; also on sheet 25
X5_LED_9: R138.1 ; also on sheet 25
X5_LED_10: R126.1 ; also on sheet 25
X5_LED_11: R128.1 ; also on sheet 25
X5_LED_12: R130.1 ; also on sheet 25
X5_LED_13: R136.1 ; also on sheet 25
X5_LED_14: R137.1 ; also on sheet 25
X5_LED_15: R139.1 ; also on sheet 25
X5_LED_16: R140.1 ; also on sheet 25
X5_LED_17: R141.1 ; also on sheet 25
X5_LED_18: R142.1 ; also on sheet 25
X5_LED_19: R143.1 ; also on sheet 25
X5_NX_ESPI_ALERT: U1.T20(PB152B/ADC_CN12) ; also on sheet 15
X5_NX_ESPI_CLK: U1.V19(PB154A/PCLKT3_3/ADC_CP15) ; also on sheet 15
X5_NX_ESPI_CS: U1.W19(PB154B/PCLKC3_3/ADC_CN15) ; also on sheet 15
X5_NX_ESPI_DATA0: U1.U19(PB156A/LRC_GPLL0T_IN) ; also on sheet 15
X5_NX_ESPI_DATA1: U1.U20(PB156B/LRC_GPLL0C_IN/VREF3_2) ; also on sheet 15
X5_NX_ESPI_RSTN: U1.T19(PB152A/ADC_CP12) ; also on sheet 15
X5_NX_I2C1_SCL: R279.2 U2.K2(PT156B) ; also on sheet 7
X5_NX_I2C1_SDA: R278.2 U2.K3(PT156A) ; also on sheet 7
X5_NX_LTPI_N_0: J8.3 R597.2 U1.R20(PB148B/PCLKC3_2/COMP3IN) ; also on sheet 15
X5_NX_LTPI_N_1: J8.5 R598.2 U1.W20(PB150B/ADC_CN11) ; also on sheet 15
X5_NX_LTPI_N_2: J8.7 U1.N19(PB144B) ; also on sheet 15
X5_NX_LTPI_N_3: J8.9 U1.V18(PB146B/ADC_CN14) ; also on sheet 15
X5_NX_LTPI_P_0: J8.2 R597.1 U1.R19(PB148A/PCLKT3_2/COMP3IP) ; also on sheet 15
X5_NX_LTPI_P_1: J8.4 R598.1 U1.V20(PB150A/ADC_CP11) ; also on sheet 15
X5_NX_LTPI_P_2: J8.6 U1.N20(PB144A) ; also on sheet 15
X5_NX_LTPI_P_3: J8.8 U1.W18(PB146A/ADC_CP14) ; also on sheet 15
X5_X3_ESPI_ALERT0n: U1.P9(PB62B) ; also on sheet 15 18
X5_X3_ESPI_ALERT1n: U1.P8(PB60B) ; also on sheet 15 18
X5_X3_ESPI_CLK: U1.T7(PB52A/PCLKT4_0) ; also on sheet 15 18
X5_X3_ESPI_CS0n: U1.R7(PB52B/PCLKC4_0) ; also on sheet 15 18
X5_X3_ESPI_CS1n: U1.V7(PB50B) ; also on sheet 15 18
X5_X3_ESPI_DQ0: U1.Y6(PB54A) ; also on sheet 15 18
X5_X3_ESPI_DQ1: U1.Y7(PB54B) ; also on sheet 15 18
X5_X3_ESPI_DQ2: U1.N7(PB56A) ; also on sheet 15 18
X5_X3_ESPI_DQ3: U1.N8(PB56B) ; also on sheet 15 18
X5_X3_ESPI_RST0n: U1.N9(PB62A) ; also on sheet 15 18
X5_X3_ESPI_RST1n: U1.R8(PB60A) ; also on sheet 15 18
X5_X3_GPIO_0: U1.W15(PB122A) ; also on sheet 19
X5_X3_GPIO_1: U1.W14(PB122B) ; also on sheet 19
X5_X3_GPIO_2: U1.V15(PB124A) ; also on sheet 19
X5_X3_GPIO_3: U1.V14(PB124B) ; also on sheet 19
X5_X3_GPIO_4: U1.Y15(PB126A) ; also on sheet 19
X5_X3_GPIO_5: U1.Y14(PB126B) ; also on sheet 19
X5_X3_GPIO_6: U1.U15(PB128A) ; also on sheet 19
X5_X3_GPIO_7: U1.U14(PB128B) ; also on sheet 19
X5_X3_GPIO_8: U1.T15(PB130A) ; also on sheet 19
X5_X3_GPIO_9: U1.T14(PB130B) ; also on sheet 19
X5_X3_I3C_SCL: U1.Y17(PB112A/PCLKT3_0/ADC_CP4) ; also on sheet 19 27
X5_X3_I3C_SDA: U1.W17(PB112B/PCLKC3_0/ADC_CN4) ; also on sheet 19 27
X5_X3_SCL_HV_I_LV_PD: U1.R17(PB118B/PCLKC3_1/COMP2IN) ; also on sheet 27
X5_X3_SCL_LV_O: U1.T16(PB120A/ADC_CP13) ; also on sheet 27
X5_X3_SDA_HV_I_LV_PD: U1.U17(PB116B/ADC_CN8) ; also on sheet 27
X5_X3_SDA_LV_O: U1.T17(PB118A/PCLKT3_1/COMP2IP) ; also on sheet 27
X5_X3_SGPIO_0: U1.R11(PB88A) ; also on sheet 19
X5_X3_SGPIO_1: U1.R10(PB88B) ; also on sheet 19
X5_X3_SGPIO_2: U1.Y10(PB90A) ; also on sheet 19
X5_X3_SGPIO_3: U1.Y11(PB90B) ; also on sheet 19
N02138: R176.2 R182.2 U10.4(DO)
N16781227: R196.1 X4.3(OUT)
N16806311: R208.1 U2.H7(PT138B/MOSI/MD0)
N16806328: R210.1 U2.H6(PT140A/MISO/MD1/OSC_HI)
N16806345: R212.1 U2.K5(PT140B/MD2)
N16833163: R213.1 U2.H4(PT142A/MD3)
N16904962: L1.2 R153.1 TP13.1
N16905216: L2.2 R154.1 TP14.1
N17075107: R168.1 U9.17(ADBUS1)
N17086765: JP19.1 R202.2
N17088630: D10.A(ANODE) R219.1
N17088632: D10.K(CATHODE) Q2.C
N17088635: Q2.B R222.1
N17088642: D11.A(ANODE) R225.2
N17656765: D7.A(ANODE) R164.2
N17726603: R215.1 U2.H3(PT142B/MCSNO/MSDO)
N17920615: R134.2 U1.P20(PB138B)
N17920616: R131.2 U1.M17(PB136A)
N17920617: R125.2 U1.R15(PB132B)
N17920618: R133.2 U1.P19(PB138A)
N17920619: R129.2 U1.P16(PB134B)
N17920620: R135.2 U1.P17(PB140A)
N17920621: R124.2 U1.R14(PB132A)
N17920622: R132.2 U1.M16(PB136B)
N17920623: R127.2 U1.N16(PB134A)
N17963993: R181.1 U9.39(BDBUS1)
N17964001: R167.1 U9.16(ADBUS0)
N18054475: R180.1 U9.38(BDBUS0)
N18573587: R155.1 U1.N15(ADC_REFP0) U1.P15(ADC_REFP1)
N18582520: R126.2 U1.W10(PB84B)
N18582536: R128.2 U1.P12(PB86A)
N18582552: R130.2 U1.R12(PB86B)
N18582568: R136.2 U1.P11(PB92B)
N18582584: R137.2 U1.V12(PB94A)
N18582600: R139.2 U1.W11(PB94B)
N18582616: R140.2 U1.V11(PB96A)
N18582632: R141.2 U1.U12(PB96B)
N18865297: FB8.1 U9.49(VREGOUT)
N18906736: R197.2 R198.1 SW8.2 SW8.4
N18906921: R199.2 R200.1 SW9.2 SW9.4
N19128599: D9.1 R214.2 R216.1 SW10.1 SW10.3
N19774364: R142.2 U1.W13(PB98A/ADC_CP5)
N19774381: R143.2 U1.W12(PB98B/ADC_CN5)
N19774469: R138.2 U1.P18(PB140B)
N20032756: R391.1 U2.R4(PR28A/PCLKT1_2)
N20032760: R395.1 U2.L2(PR4A/URC_GPLL0T_IN)
N20032764: R396.1 U2.L3(PR4B/URC_GPLL0C_IN)
N20032771: R386.1 U2.M2(PR15B)
N20032777: R387.1 U2.M1(PR17A)
N20032780: R383.1 U2.N1(PR17B)
N20032783: R385.1 U2.N2(PR19A)
N20136088: J19.7 R551.1

Not connected (* = marked no-connect by the designer): J3 4(NC)*; J19 4* 6*; U1 A5(SD0_TXDP)* A6(SD0_TXDN)* A11(SD3_TXDP)* A12(SD3_TXDN)* B1(VCCPLLSD0)* B4(SD0_REFRET)* B10(SD3_REFRET)* C5(VCCSD0)* C6(VCCSDCK)* C8(VCCSD3)* C9(VCCPLLSD3)* D7(VCCAUXSDQ0)* L13(ADC_DP1)* M12(PB108A)* M13(ADC_DN1)* M14(ADC_DN0)* M15(ADC_DP0)* N12(PB108B/VREF4_2)* N17(PB142A)* N18(PB142B)* P10(PB92A)* P13(PB106A/PCLKT4_3)* P14(PB106B/PCLKC4_3)* R9(PB64A)* R13(PB104A/ADC_CP9)* R16(PB120B/ADC_CN13)* T9(PB64B)* T13(PB104B/ADC_CN9)* U7(PB50A/VREF4_1)* U9(PB80A)* U10(PB82A)* U13(PB100A/PCLKT4_2/ADC_CP7)* V9(PB80B)* V10(PB82B)* V13(PB100B/PCLKC4_2/ADC_CN7)* W7(PB58A/PCLKT4_1)* W8(PB58B/PCLKC4_1)* W9(PB84A)* Y8(PB66A)* Y9(PB66B)* Y12(PB102A/ADC_CP6)* Y13(PB102B/ADC_CN6)*; U2 AA22(PB26B) AA23(PB28A) AA24(PB28B) AB20(PB48B/VREF5_2) AB22(PB26A) AB23(PB32A) AB24(PB32B) AB25(PB34A) AB26(PB30B) AC20(PB48A) AC21(PB46A/PCLKT5_3) AC22(PB38A) AC24(PB34B) AC25(PB36A) AC26(PB30A) AD22(PB46B/PCLKC5_3) AD23(PB38B) AD25(PB40A/PCLKT5_2) AD26(PB36B) AE24(PB44A) AE25(PB40B/PCLKC5_2) AE26(PB42A) AF24(PB44B) AF25(PB42B) H1(PT144B) J5(PT148B) K4(PT154B) K6(PT154A) L1(PR3B) L6(PR6A) L8(PR8A) M3(PR15A) M4(PR13B/PMU_WAKEUPN) M9(PR10A) N3(PR19B) N4(PR20A) N5(PR20B) N6(PR22A) N7(PR22B) P9(PR26A) T6(PR35B) T7(PR35A) T8(PR33B) U8(PR33A) V26(PB6B) W21(PB12B) W22(PB12A) W25(PB8A/ADC_CP3); U9 18(ADBUS2) 19(ADBUS3) 21(ADBUS4) 22(ADBUS5) 23(ADBUS6) 24(ADBUS7) 26(ACBUS0) 27(ACBUS1) 28(ACBUS2) 29(ACBUS3) 30(ACBUS4) 32(ACBUS5) 33(ACBUS6) 34(ACBUS7) 36(~{SUSPEND#}) 40(BDBUS2) 41(BDBUS3) 43(BDBUS4) 44(BDBUS5) 45(BDBUS6) 46(BDBUS7) 48(BCBUS0) 52(BCBUS1) 53(BCBUS2) 54(BCBUS3) 55(BCBUS4) 57(BCBUS5) 58(BCBUS6) 59(BCBUS7) 60(~{PWREN#}); U10 7(NC)*

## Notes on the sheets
sheet 8
- BANK 3
- BANK 4
- 1.8V
- 1.8V
- DNP
- LEDs Signal Map
- U1
  Pin
- Signal
- LED
- R14
- X5_LED_0
- D15
- R15
- X5_LED_1
- D16
- N16
- X5_LED_2
- D17
- P16
- X5_LED_3
- D18
- M17
- X5_LED_4
- D19
- M16
- X5_LED_5
- D20
- LTPI HEADER
- P19
- X5_LED_6
- D21
- P20
- X5_LED_7
- D22
- P17
- X5_LED_8
- D23
- P18
- X5_LED_9
- D24
- W10
- X5_LED_10
- D45
- P12
- X5_LED_11
- D35
- R12
- X5_LED_12
- D46
- P11
- X5_LED_13
- D36
- V12
- X5_LED_14
- D47
- W11
- X5_LED_15
- D38
- DNP
- V11
- X5_LED_16
- D49
- U12
- X5_LED_17
- D40
- W13
- X5_LED_18
- D51
- W12
- X5_LED_19
- D41
sheet 9
- FPGA POWER
- LFMXO5D-100-BBG400 DEVICE
sheet 10
- FTDI - UART
sheet 11
- Switch Signal Map
- U2
  Pin
- Signal
- SWITCH
- V24
- NX_BMC_DIP_SW1
- 1
- DIP SWITCH
- V25
- NX_BMC_DIP_SW2
- 2
- V23
- NX_BMC_DIP_SW3
- 3
- BANK 5
  1.8V
- V22
- NX_BMC_DIP_SW4
- 4
- U26
- NX_BMC_DIP_SW5
- 5
- W26
- NX_BMC_DIP_SW6
- 6
- W24
- NX_BMC_DIP_SW7
- 7
- W23
- NX_BMC_DIP_SW8
- 8
- FPGA GSRN
- 50ohm trace
- 2.5 x 2.0 mm 4-SMD
- PLACE X4 CLOSE TO U2
- GP BUTTON
- DNP
- BANK 1
  3.3V
- AARDVARK HEADER
sheet 12
- PROGRAMN
- BANK 0
  3.3V
- DNP
- DONE LED
- INITN LED
